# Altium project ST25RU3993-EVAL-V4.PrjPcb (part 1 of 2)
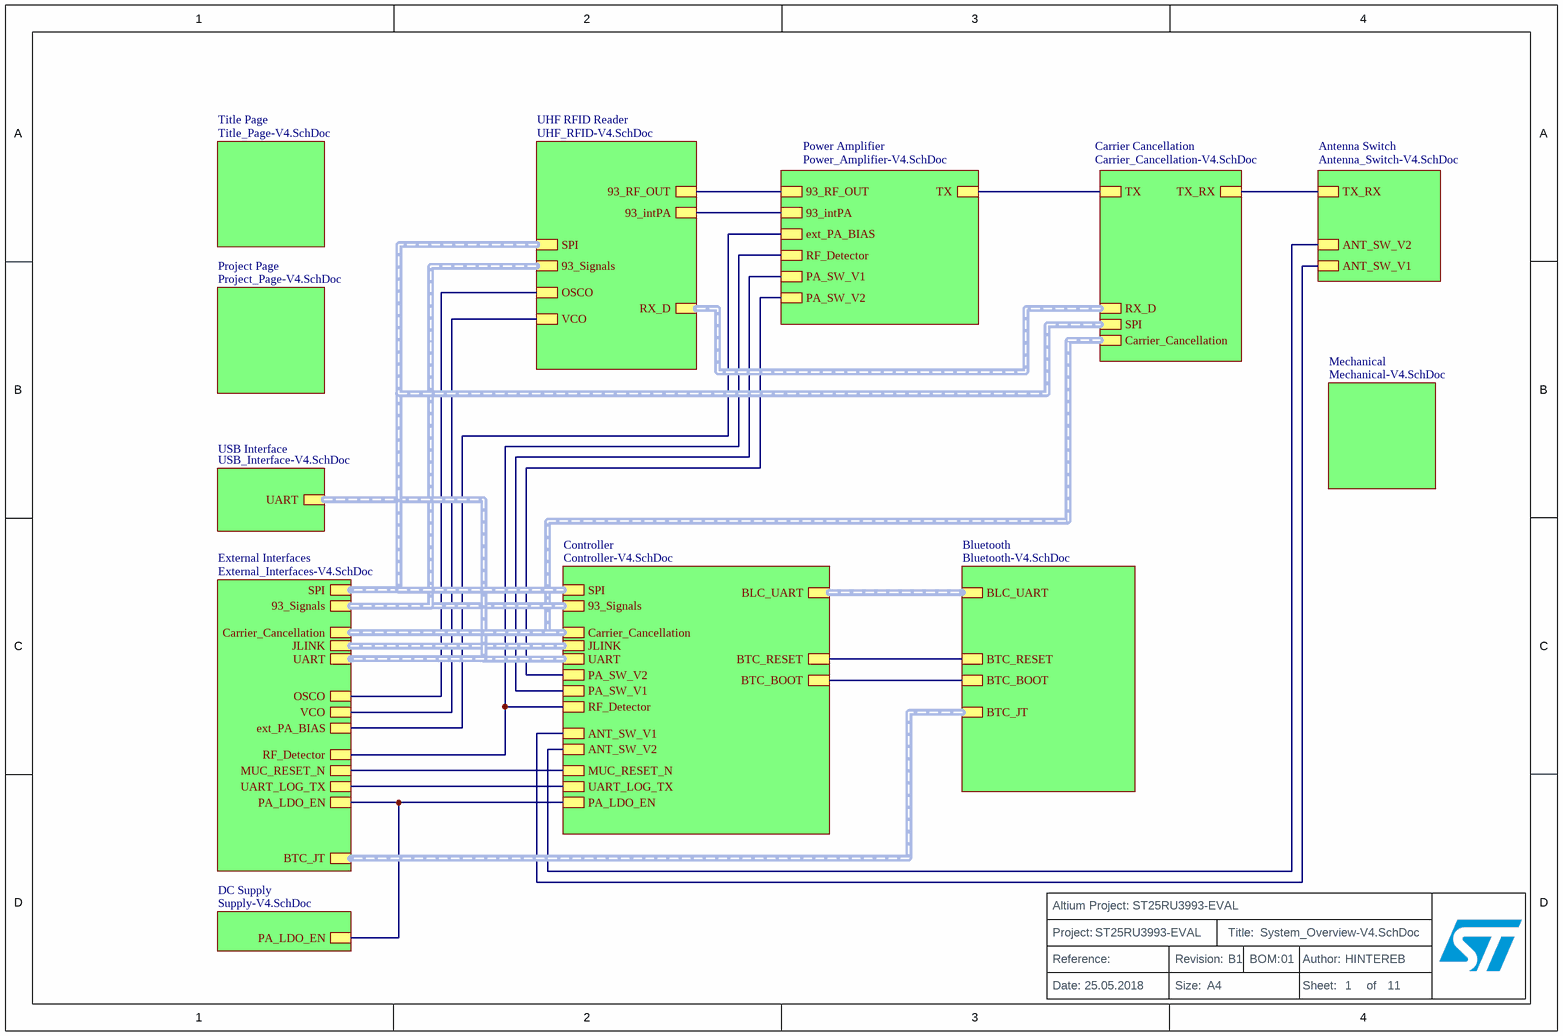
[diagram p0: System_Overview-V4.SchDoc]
ApplicationEngineer: HINTEREB; BoardCat: EVAL; BoardRef: None; BoardtypeVersion: B1; BOM Version: 01; ProjTitle: ST25RU3993-EVAL; ReleaseDate: 25.05.2018; SocProj: ST25RU3993-EVAL; SupportingApplicationEngineer: HOFERFLO; TotalNumberofSheets: 11; Variant: Standard; Version: B1
13 sheets, 327 parts. Net scope: hierarchical (ports join the sheet entries above them; power ports are global).
Board file: ST25RU3993-EVAL-V4.PcbDoc
Sheets:
  System_Overview-V4.SchDoc
    UHF RFID Reader = UHF_RFID-V4.SchDoc
    Power Amplifier = Power_Amplifier-V4.SchDoc
    Project Page = Project_Page-V4.SchDoc
    External Interfaces = External_Interfaces-V4.SchDoc
    Controller = Controller-V4.SchDoc
    Carrier Cancellation = Carrier_Cancellation-V4.SchDoc
    DC Supply = Supply-V4.SchDoc
    Title Page = Title_Page-V4.SchDoc
    USB Interface = USB_Interface-V4.SchDoc
    Bluetooth = Bluetooth-V4.SchDoc
    Mechanical = Mechanical-V4.SchDoc
    Antenna Switch = Antenna_Switch-V4.SchDoc

## Sheet System_Overview-V4.SchDoc
size A4; SheetNumber: 1; PageSetup: Record=PageOptions¦CenterHorizontal=True¦CenterVertical=True¦PrintScale=0.97¦XCorrection=1.00¦YCorrection=1.00¦PrintKind=0¦BorderSize=5000000¦LeftOffset=0¦BottomOffset=0¦Orientation=2¦PaperLength=1000¦PaperWidth=1000¦Scale=100¦PaperSource=7¦PrintQuality=-3¦MediaType=1¦DitherType=10¦PrintScaleMode=1¦PaperKind=A4¦PaperIndex=9

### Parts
TitleBlock7  Title_Block  (value not drawn)  (no BOM)

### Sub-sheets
Antenna Switch = Antenna_Switch-V4.SchDoc: ANT_SW_V2, TX_RX, ANT_SW_V1
Bluetooth = Bluetooth-V4.SchDoc: BLC_UART (harness Harness_UART_BT), BTC_JT, BTC_RESET, BTC_BOOT
Carrier Cancellation = Carrier_Cancellation-V4.SchDoc: TX, Carrier_Cancellation (harness Harness_CC), SPI (harness Harness_SPI), RX_D (harness Harness_RX_D), TX_RX
Controller = Controller-V4.SchDoc: SPI (harness Harness_SPI), UART (harness Harness_UART), 93_Signals (harness Harness_93), JLINK (harness Harness_JLINK), Carrier_Cancellation (harness Harness_CC), PA_LDO_EN, PA_SW_V2, MUC_RESET_N, UART_LOG_TX, BLC_UART (harness Harness_UART_BT), BTC_RESET, ANT_SW_V1, RF_Detector, PA_SW_V1, ANT_SW_V2, BTC_BOOT
DC Supply = Supply-V4.SchDoc: PA_LDO_EN
External Interfaces = External_Interfaces-V4.SchDoc: SPI (harness Harness_SPI), 93_Signals (harness Harness_93), Carrier_Cancellation (harness Harness_CC), JLINK (harness Harness_JLINK), PA_LDO_EN, MUC_RESET_N, UART_LOG_TX, BTC_JT (harness Harness_BTC_JT), OSCO, VCO, ext_PA_BIAS, RF_Detector, UART (harness Harness_UART)
Mechanical = Mechanical-V4.SchDoc: no entries
Power Amplifier = Power_Amplifier-V4.SchDoc: 93_RF_OUT, TX, PA_SW_V2, RF_Detector, 93_intPA, ext_PA_BIAS, PA_SW_V1
Project Page = Project_Page-V4.SchDoc: no entries
Title Page = Title_Page-V4.SchDoc: no entries
UHF RFID Reader = UHF_RFID-V4.SchDoc: 93_RF_OUT, SPI (harness Harness_SPI), 93_Signals (harness Harness_93), RX_D (harness Harness_RX_D), 93_intPA, OSCO, VCO
USB Interface = USB_Interface-V4.SchDoc: UART (harness Harness_UART)

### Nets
Detector: sheet Power Amplifier/RF_Detector, sheet External Interfaces/RF_Detector, sheet Controller/RF_Detector
EXT_PA_BIAS: sheet Power Amplifier/ext_PA_BIAS, sheet External Interfaces/ext_PA_BIAS
OSCO: sheet UHF RFID Reader/OSCO, sheet External Interfaces/OSCO
PA_LDO_EN: sheet External Interfaces/PA_LDO_EN, sheet Controller/PA_LDO_EN, sheet DC Supply/PA_LDO_EN
UART_LOG_TX: sheet External Interfaces/UART_LOG_TX, sheet Controller/UART_LOG_TX
VCO: sheet UHF RFID Reader/VCO, sheet External Interfaces/VCO
NetB1_1: sheet External Interfaces/MUC_RESET_N, sheet Controller/MUC_RESET_N
NetC107_1: sheet UHF RFID Reader/93_intPA, sheet Power Amplifier/93_intPA
NetC112_2: sheet Carrier Cancellation/TX_RX, sheet Antenna Switch/TX_RX
NetJ1_IN: sheet UHF RFID Reader/93_RF_OUT, sheet Power Amplifier/93_RF_OUT
NetJ19_1: sheet Controller/BTC_BOOT, sheet Bluetooth/BTC_BOOT
NetR74_1: sheet Controller/BTC_RESET, sheet Bluetooth/BTC_RESET
NetS1_1: sheet Power Amplifier/PA_SW_V1, sheet Controller/PA_SW_V1
NetS1_3: sheet Power Amplifier/PA_SW_V2, sheet Controller/PA_SW_V2
NetS2_1: sheet Controller/ANT_SW_V1, sheet Antenna Switch/ANT_SW_V1
NetS2_3: sheet Controller/ANT_SW_V2, sheet Antenna Switch/ANT_SW_V2
NetT2_1: sheet Power Amplifier/TX, sheet Carrier Cancellation/TX

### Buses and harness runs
harness sheet Bluetooth/BLC_UART = sheet Controller/BLC_UART
harness sheet Bluetooth/BTC_JT = sheet External Interfaces/BTC_JT
harness sheet Carrier Cancellation/Carrier_Cancellation = sheet Controller/Carrier_Cancellation = sheet External Interfaces/Carrier_Cancellation
harness sheet Carrier Cancellation/RX_D = sheet UHF RFID Reader/RX_D
harness sheet Carrier Cancellation/SPI = sheet Controller/SPI = sheet External Interfaces/SPI = sheet UHF RFID Reader/SPI
harness sheet Controller/93_Signals = sheet External Interfaces/93_Signals = sheet UHF RFID Reader/93_Signals
harness sheet Controller/JLINK = sheet External Interfaces/JLINK
harness sheet Controller/UART = sheet External Interfaces/UART = sheet USB Interface/UART

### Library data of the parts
TitleBlock7 = Title_Block: Exact Component Match: no

## Sheet UHF_RFID-V4.SchDoc
size A4; SheetNumber: 2; PageSetup: Record=PageOptions¦CenterHorizontal=True¦CenterVertical=True¦PrintScale=0.97¦XCorrection=1.00¦YCorrection=1.00¦PrintKind=0¦BorderSize=5000000¦LeftOffset=0¦BottomOffset=0¦Orientation=2¦PaperLength=1000¦PaperWidth=1000¦Scale=100¦PaperSource=7¦PrintQuality=-4¦MediaType=1¦DitherType=10¦PaperKind=A4¦PrintScaleMode=1
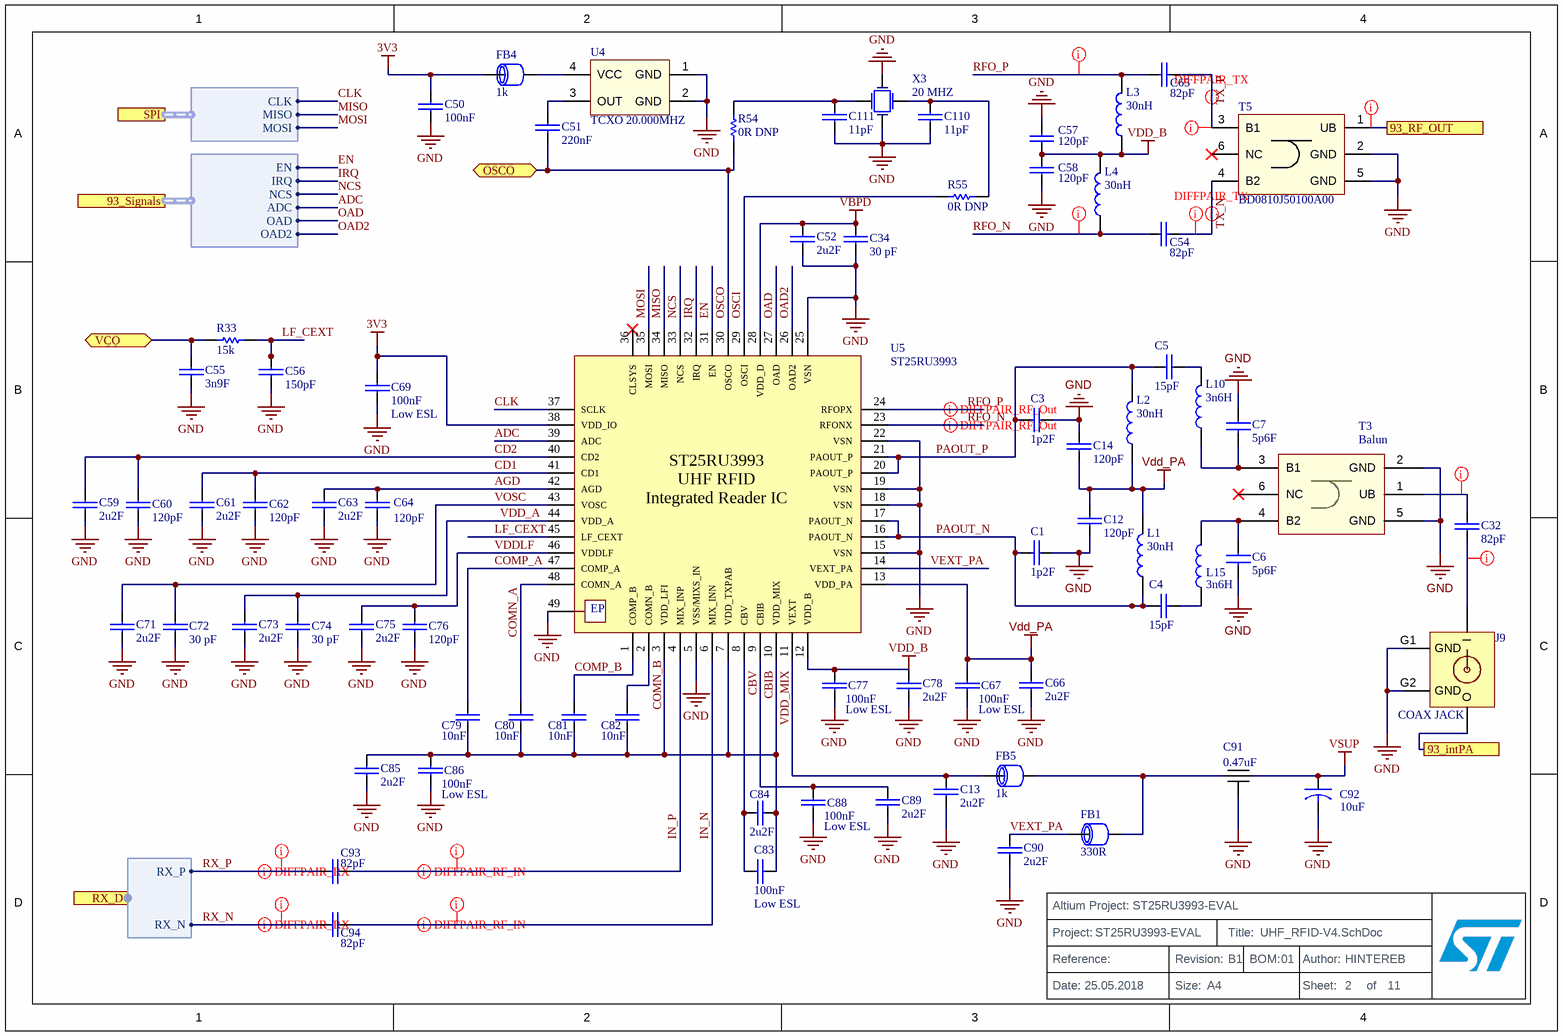
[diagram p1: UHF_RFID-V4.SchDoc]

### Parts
C1  1p2F  [C0402-RF]
C3  1p2F  [C0402-RF]
C4  15pF  [C0402-RF]
C5  15pF  [C0402-RF]
C6  5p6F  [C0402-RF]
C7  5p6F  [C0402-RF]
C12  120pF  [C0201-RF]
C13  2u2F  [C0201-RF]
C14  120pF  [C0201-RF]
C32  82pF  [C0402-RF]
C34  30 pF  [C0201-RF]
C50  100nF  [C0402-RF]
C51  220nF  [C0402-RF]
C52  2u2F  [C0201-RF]
C54  82pF  [C0402-RF]
C55  3n9F  [C0402-RF]
C56  150pF  [C0402-RF]
C57  120pF  [C0201-RF]
C58  120pF  [C0201-RF]
C59  2u2F  [C0201-RF]
C60  120pF  [C0201-RF]
C61  2u2F  [C0201-RF]
C62  120pF  [C0201-RF]
C63  2u2F  [C0201-RF]
C64  120pF  [C0201-RF]
C65  82pF  [C0402-RF]
C66  2u2F  [C0201-RF]
C67  100nF  Features: Low ESL  [C0402-LLL]
C69  100nF  Features: Low ESL  [C0402-LLL]
C71  2u2F  [C0201-RF]
C72  30 pF  [C0201-RF]
C73  2u2F  [C0201-RF]
C74  30 pF  [C0201-RF]
C75  2u2F  [C0201-RF]
C76  120pF  [C0201-RF]
C77  100nF  Features: Low ESL  [C0402-LLL]
C78  2u2F  [C0201-RF]
C79  10nF  [C0201-ss]
C80  10nF  [C0201-ss]
C81  10nF  [C0201-ss]
C82  10nF  [C0201-ss]
C83  100nF  Features: Low ESL  [C0402-LLL]
C84  2u2F  [C0201-RF]
C85  2u2F  [C0201-RF]
C86  100nF  Features: Low ESL  [C0402-LLL]
C88  100nF  Features: Low ESL  [C0402-LLL]
C89  2u2F  [C0201-RF]
C90  2u2F  [C0201-RF]
C91  0.47uF  [NFM18PS]
C92  10uF  [2917(7343)]
C93  82pF  [C0402-RF]
C94  82pF  [C0402-RF]
C110  11pF  [C0402-RF]
C111  11pF  [C0402-RF]
FB1  330R  [FB0402-RF]
FB4  1k  [L0402-RF]
FB5  1k  [L0402-RF]
J9  COAX JACK  [MS-156HF]
L1  30nH  [L0402-RF]
L2  30nH  [L0402-RF]
L3  30nH  [L0402-RF]
L4  30nH  [L0402-RF]
L10  3n6H  [L0402-RF]
L15  3n6H  [L0402-RF]
R33  15k  [R0402-RF]
R54  0R DNP  [R0402-RF]
R55  0R DNP  [R0402-RF]
T3  Balun  [JTI-0900BL15C050]
T5  BD0810J50100A00  [BD0810J50100AHF]
TitleBlock5  Title_Block  (value not drawn)  (no BOM)
U4  TCXO 20.000MHZ  [3.2 x 2.5 mm SMD]
U5  ST25RU3993  [ST25RU3993_QFN48_0.5mm_pitch]
X3  20 MHZ  [NX3225SA]

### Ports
93_intPA, 93_RF_OUT, 93_Signals (harness Harness_93), OSCO (bidir), RX_D (harness Harness_RX_D), SPI (harness Harness_SPI), VCO (bidir)

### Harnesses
Harness_SPI: MISO, MOSI, CLK
Harness_93: IRQ, EN, NCS, ADC, OAD, OAD2
Harness_RX_D: RX_P, RX_N

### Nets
3V3: C50.1 C69.1 FB4.1 U5.38(VDD_IO)
GND: C1.2 C3.2 C6.2 C7.1 C12.2 C13.2 C14.1 C34.2 C50.2 C52.1 C55.2 C56.2 C57.1 C58.2 C59.2 C60.2 C61.2 C62.2 C63.2 C64.2 C66.2 C67.2 C69.2 C71.2 C72.2 C73.2 C74.2 C75.2 C76.2 C77.2 C78.2 C85.2 C86.2 C88.2 C89.2 C90.2 C91.2 C92.2 C110.2 C111.2 J9.G1(GND) J9.G2(GND) T3.2(GND) T3.5(GND) T5.2(GND) T5.5(GND) U4.1(GND) U4.2(GND) U5.5(VSS/MIXS_IN) U5.15(VSN) U5.18(VSN) U5.19(VSN) U5.22(VSN) U5.25(VSN) U5.49(EP) X3.2(GND) X3.4(GND)
VBPD: C34.1 C52.2 U5.28(VDD_D)
VDD_B: C57.2 C58.1 C77.1 C78.1 L3.1 L4.2 U5.12(VDD_B)
Vdd_PA: C12.1 C14.2 C66.1 C67.1 L1.2 L2.1 U5.13(VDD_PA)
VSUP: C91.3 C92.1
ADC: U5.39(ADC) ; port 93_Signals.ADC
AGD: C63.1 C64.1 U5.42(AGD)
CBIB: C88.1 C89.1 U5.9(CBIB)
CBV: C83.1 C84.1 U5.8(CBV)
CD1: C61.1 C62.1 U5.41(CD1)
CD2: C59.1 C60.1 U5.40(CD2)
CLK: U5.37(SCLK) ; port SPI.CLK
COMN_A: C80.1 U5.48(COMN_A)
COMN_B: C82.1 U5.2(COMN_B)
COMP_A: C79.1 U5.47(COMP_A)
COMP_B: C81.1 U5.1(COMP_B)
EN: U5.31(EN) ; port 93_Signals.EN
IN_N: C94.2 U5.6(MIX_INN)
IN_P: C93.2 U5.4(MIX_INP)
IRQ: U5.32(IRQ) ; port 93_Signals.IRQ
LF_CEXT: C56.1 R33.2 U5.45(LF_CEXT)
MISO: U5.34(MISO) ; port SPI.MISO
MOSI: U5.35(MOSI) ; port SPI.MOSI
NCS: U5.33(NCS) ; port 93_Signals.NCS
OAD: U5.27(OAD) ; port 93_Signals.OAD
OAD2: U5.26(OAD2) ; port 93_Signals.OAD2
OSCI: R55.2 U5.29(OSCI)
OSCO: C51.2 R54.1 U5.30(OSCO) ; port OSCO
PAOUT_N: C1.1 C4.1 L1.1 U5.16(PAOUT_N) U5.17(PAOUT_N)
PAOUT_P: C3.1 C5.1 L2.2 U5.20(PAOUT_P) U5.21(PAOUT_P)
RFO_N: C54.1 L4.1 U5.23(RFONX)
RFO_P: C65.1 L3.2 U5.24(RFOPX)
RX_N: C94.1 ; port RX_D.RX_N
RX_P: C93.1 ; port RX_D.RX_P
TX_N: C54.2 T5.4(B2)
TX_P: C65.2 T5.3(B1)
VCO: C55.1 R33.1 ; port VCO
VDD_A: C73.1 C74.1 U5.44(VDD_A)
VDD_MIX: C79.2 C80.2 C81.2 C82.2 C83.2 C84.2 C85.1 C86.1 U5.3(VDD_LFI) U5.7(VDD_TXPAB) U5.10(VDD_MIX)
VDDLF: C75.1 C76.1 U5.46(VDDLF)
VEXT_PA: C90.1 FB1.1 U5.14(VEXT_PA)
VOSC: C71.1 C72.1 U5.43(VOSC)
NetC4_2: C4.2 L15.1
NetC5_2: C5.2 L10.2
NetC6_1: C6.1 L15.2 T3.4(B2)
NetC7_2: C7.2 L10.1 T3.3(B1)
NetC13_1: C13.1 FB5.1 U5.11(VEXT)
NetC32_1: C32.1 J9.IN(I)
NetC32_2: C32.2 T3.1(UB)
NetC51_1: C51.1 U4.3(OUT)
NetC91_1: C91.1 FB1.2 FB5.2
NetC107_1: J9.OUT(O) ; port 93_intPA
NetC110_1: C110.1 R55.1 X3.3
NetC111_1: C111.1 R54.2 X3.1
NetFB4_2: FB4.2 U4.4(VCC)
NetJ1_IN: T5.1(UB) ; port 93_RF_OUT

Not connected (* = marked no-connect by the designer): T3 6(NC)*; T5 6(NC)*; U5 36(CLSYS)*

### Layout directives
net class SE_CPWG: NetC32_1, NetC32_2, NetJ1_IN
differential pair: IN_N, IN_P, RFO_N, RFO_P, RX_N, RX_P, TX_N, TX_P
net class Differential_RF: IN_N, IN_P, RFO_N, RFO_P, RX_N, RX_P, TX_N, TX_P

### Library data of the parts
C1 C3 = GRM1555C1H1R2WA01D: CAP CER 1.2PF 50V NP0 0402; Manufacturer: Murata Electronics North America; Tolerance: ±0.05pF; Temperature Coefficient: C0G, NP0; Exact Component Match: yes
C4 C5 = GRM1555C1H150GA01D: CAP CER 15PF 50V NP0 0402; Manufacturer: Murata Electronics North America; Tolerance: ±2%; Temperature Coefficient: C0G, NP0; Exact Component Match: yes
C6 C7 = GJM1555C1H5R6CB01D: CAP CER 5.6PF 50V NP0 0402; Manufacturer 1: Murata Electronics North America; Tolerance: ±0.25pF; Temperature Coefficient: C0G, NP0; Frequency Min: 380; Frequency Max: 960; Gain: 32; RF IC Case Style: QFN; No. of Pins: 16; Supply Voltage Min: 3; Supply Voltage Max: 5; Frequency Range: 380MHz to 960; RF Type: General Purpose; Supply Current: 320; Supply Voltage Range: 3V to 5V<!--FANDB--><div class="features-and-benefits-container"><div class="features-and-benefits-description"><span class="features-benefits-value">The RFPA0133 is a 3 to 5V high efficiency programmable gain Power Amplifier designed to offer saturated efficiency greater than 60% over a range of frequencies from 380 to 960MHz. The device is manufactured on an advanced Gallium Arsenide Heterojunction Bipolar Transistor (HBT) process.</span></div><div class="features-and-benefits-list"><ul class="features-and-benefits-list-list"><li class="features-and-benefits-list-item">0.5W CW Output power at 3.6V</li><li class="features-and-benefits-list-item">1W CW Output power at 5V</li><li class="features-and-benefits-list-item">32dB Small signal gain at 900; Exact Component Match: yes
C12 C14 C57 C58 C60 C62 C64 C76 = GRM0335C1H121JA01D: CAP CER 120PF 50V C0G/NP0 0201; Manufacturer: Murata Electronics North America; Tolerance: ±5%; Temperature Coefficient: C0G, NP0; Exact Component Match: no
C13 C52 C59 C61 C63 C66 C71 C73 C75 C78 C84 C85 C89 C90 = GRM033R60J225ME15D: CAP CER 2.2UF 6.3V X5R 0201; Manufacturer 1: Murata Electronics North America; Capacitance: 2.2µF; Tolerance: ±20%; Exact Component Match: no
C32 C54 C65 C93 C94 = GRM1555C1H820GA01J: CAP CER 82PF 50V C0G/NP0 0402; Manufacturer: Murata Electronics North America; Tolerance: ±2%; Temperature Coefficient: C0G, NP0; Filter Type: Signal Line; Number of Lines: 1; Impedance @ Frequency: 1 kOhm @ 100MHz; Current Rating (Max): 250mA; DC Resistance (DCR) (Max): 1.1 Ohm; Type: Zener; Voltage - Reverse Standoff (Typ): 3V; Voltage - Breakdown (Min): 6V; Voltage - Clamping (Max) @ Ipp: 17V; Current - Peak Pulse (10/1000µs): 1A (8/20µs); Power - Peak Pulse: 40W; Power Line Protection: No; Capacitance @ Frequency: 0.4pF @ 200MHz ~ 3GHz
C34 C72 C74 = GRM0335C1H300GA01D: CAP CER 30PF 50V C0G/NP0 0201; Manufacturer: Murata Electronics North America; Tolerance: ±2%; Temperature Coefficient: C0G, NP0; Exact Component Match: no
C50 = GRM155R71C104KA88D: CAP CER 0.1UF 16V X7R 0402; Manufacturer: Murata Electronics North America; Capacitance: 0.10µF; Tolerance: ±10%; Exact Component Match: no
C51 = GRM155R6YA224KE01D: CAP CER 0.22UF 35V X5R 0402; Manufacturer: Murata Electronics North America; Tolerance: ±10%; Exact Component Match: no
C55 = GRM1557U1A392JA01D: CAP CER 3900PF 10V U2J 0402; Manufacturer: Murata Electronics North America; Tolerance: ±5%; Exact Component Match: no
C56 = GRM1555C1H151FA01D: CAP CER 150PF 50V NP0 0402; Manufacturer: Murata Electronics North America; Tolerance: ±1%; Temperature Coefficient: C0G, NP0; Notification: Current market demand for these product types have resulted in fluctuating and extending lead times. Lead times may differ.; Exact Component Match: no
C67 C69 C77 C83 C86 C88 = LLL153C80J104ME01E: CAP CER 0.1UF 6.3V X6S 0204; Manufacturer: Murata Electronics North America; Tolerance: ±20%; Type: Steering (Rail to Rail); Voltage - Reverse Standoff (Typ): 5.25V; Voltage - Breakdown (Min): 6V; Power - Peak Pulse: 500W; Power Line Protection: Yes; Exact Component Match: no
C79-C82 = GRM033R61E103KA12D: CAP CER 10000PF 10V X7R 0201; Manufacturer 1: Murata Electronics North America; Manufacturer Part Number 1: GRM033R71A103KA01D; Tolerance: ±10%; Exact Component Match: no
C91 = NFM18PS474R0J3D: CAP FEEDTHRU 0.47UF 6.3V 0603; Manufacturer: Murata Electronics North America; Capacitance: 0.47µF; Tolerance: ±20%; Current: 2A; DC Resistance (DCR) (Max): 30 mOhm; Type: Polymer; ESR (Equivalent Series Resistance): 70 mOhm; Lifetime @ Temp.: 1000 Hrs @ 105°C; Ripple Current - High Frequency: 1A @ 100kHz; Surface Mount Land Size: 0.287" L x 0.169" W (7.30mm x 4.30mm); Exact Component Match: no
C92 = ECASD41C106M060K00: CAP POLYMER 10UF 20% 16V SMD; Manufacturer: Murata; Product Training Modules: Polymer Aluminum Electrolytic Capacitors Using Murata's Polymer Aluminum Capacitors to Replace Tantalum; Catalog Drawings: ECAS Series End_D4 ECAS Series Side; Featured Product: ECAS Series Polymer Aluminum Electrolytic Capacitors; EDA / CAD Models: Download from Accelerated Designs; Capacitance: 10µF; ESR (Equivalent Series Resistance): 60 mOhm @ 100kHz; Lifetime @ Temp.: 1000 Hrs @ 105°C; Polarization: Polar; Ripple Current: 1A; Surface Mount Land Size: 0.287" L x 0.169" W (7.30mm x 4.30mm); Online Catalog: ECAS Series; Other Names: 490-5482-2
C110 C111 = GJM1555C1H110GB01D (2): CAP CER 11PF 50V C0G/NP0 0402; Manufacturer: Murata Electronics North America; Tolerance: ±2%; Temperature Coefficient: C0G, NP0; Exact Component Match: no
FB1 = BLM15PX331SN1D: FERRITE BEAD 330 OHM 0402 1LN; Manufacturer: Murata Electronics North America; Filter Type: Power Line; Current Rating (Max): 1.2A; DC Resistance (DCR) (Max): 150 mOhm; Exact Component Match: no
FB4 FB5 = BLM15HG102SN1D: FERRITE BEAD 1 KOHM 0402 1LN; Manufacturer: Murata Electronics North America; Filter Type: Signal Line; Number of Lines: 1; Impedance @ Frequency: 1 kOhm @ 100MHz; Current Rating (Max): 250mA; DC Resistance (DCR) (Max): 1.1 Ohm; Exact Component Match: no
J9 = MS-156HF: CONN COAX JACK STR 50 OHM SMD; Manufacturer 1: Hirose Electric Co Ltd; Manufacturer Part Number 1: MS-156HF(01); Connector Style: Coaxial Switch - 4mm Plug Dia; Connector Type: Receptacle, Female Socket; Contact Termination: Solder; Impedance: 50 Ohm; Frequency - Max: 6GHz; Body Material: Phosphor Bronze; Body Finish: Gold; Center Contact Material: Beryllium Copper; Dielectric Material: Polyamide (PA), Nylon 6T; Coupler Type: Standard; Frequency: 700MHz ~ 1GHz; Coupling Factor: 10.9dB; Insertion Loss: 0.21dB; Power - Max: 2W; Return Loss: 17.5dB; Exact Component Match: no
L1 L2 = LQW15AN30NG00D: FIXED IND 30NH 270MA 580 MOHM; Manufacturer: Murata Electronics North America; Type: Wirewound; Material - Core: Non-Magnetic; Tolerance: ±2%; Shielding: Unshielded; DC Resistance (DCR): 580 mOhm Max; Q @ Freq: 25 @ 250MHz; Frequency - Self Resonant: 3.3GHz; Frequency - Test: 100MHz; Exact Component Match: yes
L3 L4 = LQW15AN30NG00D: FIXED IND 30NH 270MA 580 MOHM; Manufacturer: Murata Electronics North America; Type: Wirewound; Material - Core: Non-Magnetic; Tolerance: ±2%; Shielding: Unshielded; DC Resistance (DCR): 580 mOhm Max; Q @ Freq: 25 @ 250MHz; Frequency - Self Resonant: 3.3GHz; Frequency - Test: 100MHz; Exact Component Match: no
L10 L15 = LQW15AN3N6C10D: FIXED IND 3.6NH 900MA 40 MOHM; Manufacturer: Murata Electronics North America; Type: Wirewound; Material - Core: Non-Magnetic; Tolerance: ±0.2nH; Shielding: Unshielded; DC Resistance (DCR): 40 mOhm Max; Q @ Freq: 30 @ 250MHz; Frequency - Self Resonant: 9.5GHz; Frequency - Test: 100MHz; Exact Component Match: yes
R33 = ERJ-2GEJ153X: RES SMD 15K OHM 5% 1/10W 0402; Manufacturer: Panasonic Electronic Components; Power (Watts): 0.1W, 1/10W; Temperature Coefficient: ±200ppm/°C; Exact Component Match: no
R54 R55 = RC0402JR-070RL: RES SMD 0.0OHM JUMPER 1/16W 0402; Manufacturer: Yageo; Resistance (Ohms): 0.0; Power (Watts): 0.063W, 1/16W; Exact Component Match: no
T3 = 1:1 BALUN 900MHZ - 0900BL15C050: 1:1 BALUN- 900MHZ 50/50 Ohm; Manufacturer: Johanson Technology Inc; Manufacturer Part Number: 0900BL15C050E; Component_Description: BALUN GSM/DCS/PCS/CDMA 900MHZ; Frequency Range: 800 ~ 1000MHz; Phase Difference: 180° ±10; Insertion Loss (Max): 1.2dB; Return Loss (Min): 9.5dB; Exact Component Match: no
T5 = BD0810J50100AHF: XFRMR BALUN RF 800-1000MHZ 0805; Manufacturer: Anaren; Frequency Range: 800MHz ~ 1GHz; Impedance - Unbalanced/Balanced: 50 / 100 Ohm; Phase Difference: 1°; Insertion Loss (Max): 0.95dB; Return Loss (Min): 13dB; Exact Component Match: no
TitleBlock5 = Title_Block: Exact Component Match: no
U4 = TXETDCSANF-20.000000: OSC TCXO 20.0000MHZ CLP SW SMD; Manufacturer: Taitien; Output: Clipped Sine Wave; Voltage - Supply: 2.8 V ~ 3.3 V; Frequency Stability: ±2.5ppm; Current - Supply (Max): 2mA
U5 = ST25RU3993: UHF EPC CLASS1 GEN2 READER; Manufacturer: ST Microelectronics; Manufacturer Part Number: ST25RU3993-BQFT; Frequency: 860MHz ~ 960MHz; Standards: EPC, ISO 18000-6; Voltage - Supply: 2.7 V ~ 3.6 V; Exact Component Match: yes
X3 = NX3225SA-20.000000MHZ-B2: CRYSTAL 20.0000MHZ 7.2PF SMD; Manufacturer: NDK; Frequency: 20MHz; Frequency Stability: ±15ppm; Frequency Tolerance: ±10ppm; ESR (Equivalent Series Resistance): 80 Ohm; Operating Mode: Fundamental; Exact Component Match: no

## Sheet Power_Amplifier-V4.SchDoc
size A4; SheetNumber: 3; PageSetup: Record=PageOptions¦CenterHorizontal=True¦CenterVertical=True¦PrintScale=0.97¦XCorrection=1.00¦YCorrection=1.00¦PrintKind=0¦BorderSize=5000000¦LeftOffset=0¦BottomOffset=0¦Orientation=2¦PaperLength=1000¦PaperWidth=1000¦Scale=100¦PaperSource=7¦PrintQuality=-4¦MediaType=1¦DitherType=10¦PaperKind=A4¦PrintScaleMode=1
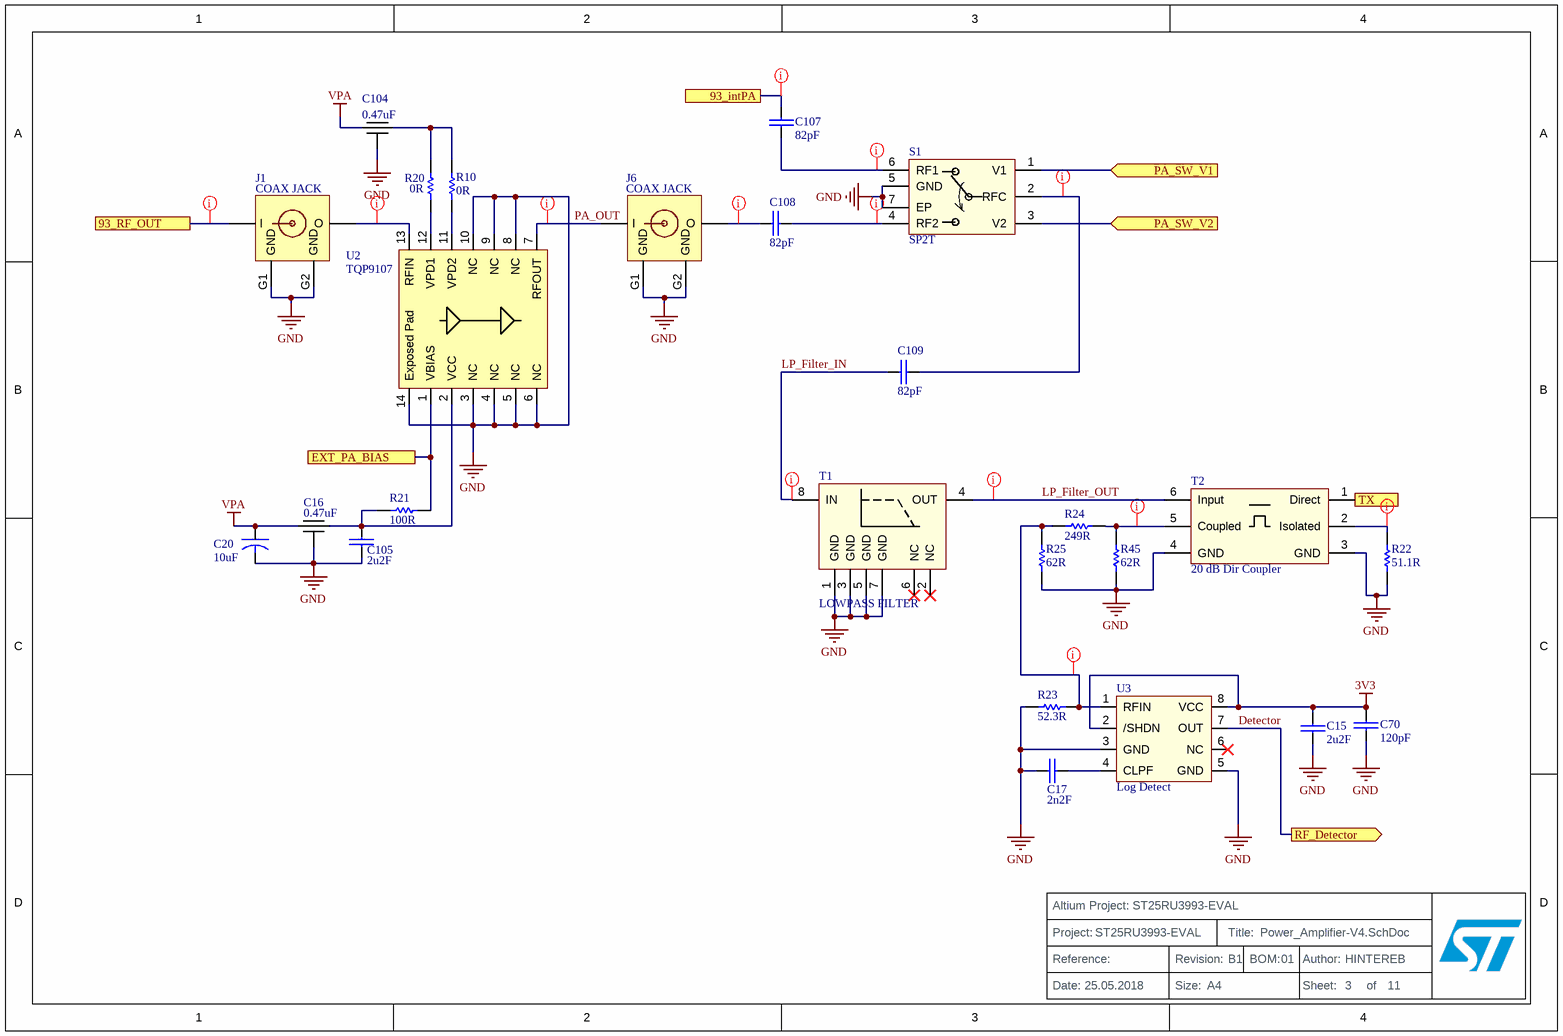
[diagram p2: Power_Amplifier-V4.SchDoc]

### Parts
C15  2u2F  [C0201-RF]
C16  0.47uF  [NFM18PS]
C17  2n2F  [C0402-RF]
C20  10uF  [2917(7343)]
C70  120pF  [C0201-RF]
C104  0.47uF  [NFM18PS]
C105  2u2F  [C0201-RF]
C107  82pF  [C0402-RF]
C108  82pF  [C0402-RF]
C109  82pF  [C0402-RF]
J1  COAX JACK  [MS-156HF_SAW]
J6  COAX JACK  [MS-156HF]
R10  0R  [R0402-RF]
R20  0R  [R0402-RF]
R21  100R  [R0402-RF]
R22  51.1R  [R0402-RF]
R23  52.3R  [R0402-RF]
R24  249R  [R0402-RF]
R25  62R  [R0402-RF]
R45  62R  [R0402-RF]
S1  SP2T  [SKY13431-374LF]
T1  LOWPASS FILTER  [JTI-0900LP15B0063]
T2  20 dB Dir Coupler  [DC0710J5010AHF]
TitleBlock3  Title_Block  (value not drawn)  (no BOM)
U2  TQP9107  [TQP9107]
U3  Log Detect  [MAX4003]

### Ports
93_intPA, 93_RF_OUT, EXT_PA_BIAS, PA_SW_V1 (in), PA_SW_V2 (in), RF_Detector (out), TX (out)

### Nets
3V3: C15.1 C70.1 U3.2(/SHDN) U3.8(VCC)
GND: C15.2 C16.2 C17.1 C20.2 C70.2 C104.2 C105.2 J1.G1(GND) J1.G2(GND) J6.G1(GND) J6.G2(GND) R22.1 R23.1 R25.1 R45.1 S1.5(GND) S1.7(EP) T1.1(GND) T1.3(GND) T1.5(GND) T1.7(GND) T2.3(GND) T2.4(GND) U2.3(NC) U2.4(NC) U2.5(NC) U2.6(NC) U2.8(NC) U2.9(NC) U2.10(NC) U2.14(Exposed_Pad) U3.3(GND) U3.5(GND)
VPA: C16.3 C20.1 C104.1
Detector: U3.7(OUT) ; port RF_Detector
EXT_PA_BIAS: R21.2 U2.1(VBIAS) ; port EXT_PA_BIAS
LP_Filter_IN: C109.2 T1.8(IN)
LP_Filter_OUT: T1.4(OUT) T2.6(Input)
PA_OUT: J6.IN(I) U2.7(RFOUT)
NetC16_1: C16.1 C105.1 R21.1 U2.2(VCC)
NetC17_2: C17.2 U3.4(CLPF)
NetC104_3: C104.3 R10.2 R20.2
NetC107_1: C107.1 ; port 93_intPA
NetC107_2: C107.2 S1.6(RF1)
NetC108_1: C108.1 S1.4(RF2)
NetC108_2: C108.2 J6.OUT(O)
NetC109_1: C109.1 S1.2(RFC)
NetJ1_IN: J1.IN(I) ; port 93_RF_OUT
NetJ1_OUT: J1.OUT(O) U2.13(RFIN)
NetR10_1: R10.1 U2.11(VPD2)
NetR20_1: R20.1 U2.12(VPD1)
NetR22_2: R22.2 T2.2(Isolated)
NetR23_2: R23.2 R24.1 R25.2 U3.1(RFIN)
NetR24_2: R24.2 R45.2 T2.5(Coupled)
NetS1_1: S1.1(V1) ; port PA_SW_V1
NetS1_3: S1.3(V2) ; port PA_SW_V2
NetT2_1: T2.1(Direct) ; port TX

Not connected (* = marked no-connect by the designer): T1 2(NC)* 6(NC)*; U3 6(NC)*

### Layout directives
net class SE_CPWG: LP_Filter_IN, LP_Filter_OUT, NetC107_1, NetC107_2, NetC108_1, NetC108_2, NetC109_1, NetJ1_IN, NetJ1_OUT, NetR22_2, NetR23_2, NetR24_2, PA_OUT

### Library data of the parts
C15 C105 = GRM033R60J225ME15D: as C13 on sheet UHF_RFID-V4
C16 C104 = NFM18PS474R0J3D: as C91 on sheet UHF_RFID-V4
C17 = GRM155R71H222KA01D (2): CAP CER 2.2NF 50V X7R 0402; Manufacturer: Murata Electronics North America; Tolerance: ±10%; Notification: Current market demand for these product types have resulted in fluctuating and extending lead times. Lead times may differ.; Exact Component Match: no
C20 = ECASD41C106M060K00: as C92 on sheet UHF_RFID-V4
C70 = GRM0335C1H121JA01D: as C12 on sheet UHF_RFID-V4
C107-C109 = GRM1555C1H820GA01J: as C32 on sheet UHF_RFID-V4
J1 = MS-156HF_SAW: CONN COAX JACK STR 50 OHM SMD; Manufacturer 1: Hirose Electric Co Ltd; Manufacturer Part Number 1: MS-156HF(01); Connector Style: Coaxial Switch - 4mm Plug Dia; Connector Type: Receptacle, Female Socket; Contact Termination: Solder; Impedance: 50 Ohm; Frequency - Max: 6GHz; Body Material: Phosphor Bronze; Body Finish: Gold; Center Contact Material: Beryllium Copper; Dielectric Material: Polyamide (PA), Nylon 6T; Coupler Type: Standard; Frequency: 700MHz ~ 1GHz; Coupling Factor: 10.9dB; Insertion Loss: 0.21dB; Power - Max: 2W; Return Loss: 17.5dB; Exact Component Match: no; Capacitance: 2.2µF; Tolerance: ±20%; Voltage - Rated: 10V; Current: 4A; DC Resistance (DCR) (Max): 10 mOhm; Material - Core: Air; Shielding: Unshielded; DC Resistance (DCR): 1.25 Ohm Max
J6 = MS-156HF: as J9 on sheet UHF_RFID-V4
R10 R20 = RC0402JR-070RL: as R54 on sheet UHF_RFID-V4
R21 = RC0402FR-07100RL: RES SMD 100 OHM 1% 1/16W 0402; Manufacturer: Yageo; Resistance (Ohms): 100; Power (Watts): 0.063W, 1/16W; Temperature Coefficient: ±100ppm/°C; Exact Component Match: no
R22 = RC0402FR-0751R1L: RES SMD 51.1 OHM 1% 1/16W 0402; Manufacturer: Yageo; Power (Watts): 0.063W, 1/16W; Temperature Coefficient: ±100ppm/°C; Exact Component Match: no
R23 = ERJ2RKF52R3X: RES SMD 52R3 1% 0.1W 0402; Manufacturer: Panasonic Electronic Components; Manufacturer Part Number: ERJ-2RKF52R3X; Power (Watts): 0.1W, 1/10W; Temperature Coefficient: ±100ppm/°C; Exact Component Match: no
R24 = RC0402FR-07249RL: RES SMD 249 OHM 1% 1/16W 0402; Manufacturer: Yageo; Power (Watts): 0.063W, 1/16W; Temperature Coefficient: ±100ppm/°C; Exact Component Match: no
R25 R45 = RC0402FR-0762RL: RES SMD 62 OHM 1% 1/16W 0402; Manufacturer: Yageo; Power (Watts): 0.063W, 1/16W; Temperature Coefficient: ±100ppm/°C; Exact Component Match: no
S1 = SKY13431-374LF: IC SWITCH SP2T; Manufacturer: Skyworks Solutions Inc.; Frequency - Lower: 500MHz; Isolation @ Frequency: 20dB @ 5.8GHz (typ); Insertion Loss @ Frequency: 0.8dB @ 5.8GHz; IIP3: 57dBm (typ); Circuit: SPDT; P1dB: 36dBm; Impedance: 50 Ohm; Voltage - Supply: 2.5 V ~ 5 V; RF Type: WiMax, WLAN; Exact Component Match: no
T1 = 0900LP15B0063: FILTER LOWPASS 863-960MHZ; Manufacturer: Johanson Technology Inc.; Manufacturer Part Number: 0900LP15B0063E; Exact Component Match: no
T2 = DC1722J5020AHF: COUPLER 20DB 1700-2200MHZ 0805; Manufacturer: Anaren; Coupler Type: Standard; Frequency: 1.7GHz ~ 2.2GHz; Coupling Factor: 19.9dB; Insertion Loss: 0.17dB; Power - Max: 2W; Return Loss: 22.5dB; Exact Component Match: no
TitleBlock3 = Title_Block: Exact Component Match: no
U2 = TQP9107: 699 – 960 MHz 2-stage Power Amplifier; Manufacturer: Qorvo
U3 = MAX4003EUA+T: IC LOG AMP RF DETECT 45DB 8-MSOP; Manufacturer: Maxim Integrated; Frequency: 100MHz ~ 2.5GHz; RF Type: Cellular, TDMA, CDMA, GPRS, GSM; Input Range: -45dBm ~ 0dBm; Voltage - Supply: 2.7 V ~ 5 V; Exact Component Match: no

## Sheet Project_Page-V4.SchDoc
size A4
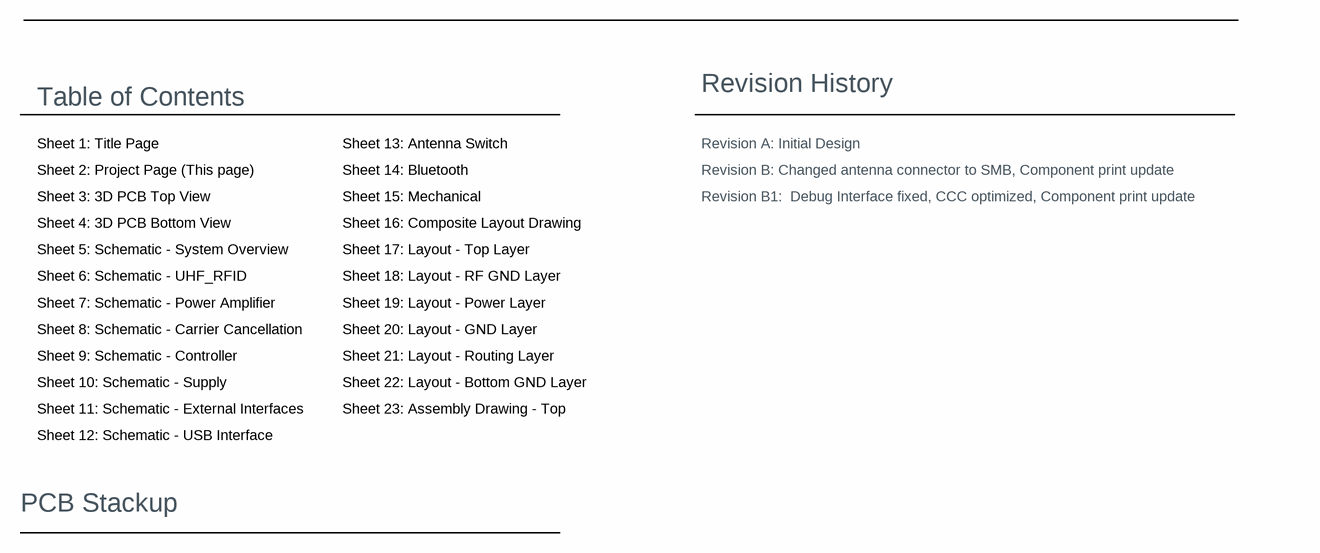
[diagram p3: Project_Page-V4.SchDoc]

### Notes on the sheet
- Table of Contents
- Sheet 1: Title Page
- Sheet 13: Antenna Switch
- Revision History
- Revision A: Initial Design
- Sheet 2: Project Page (This page)
- Sheet 3: 3D PCB Top View
- Sheet 15: Mechanical
- Sheet 14: Bluetooth
- Revision B: Changed antenna connector to SMB, Component print update
- Revision B1:  Debug Interface fixed, CCC optimized, Component print update
- Sheet 5: Schematic - System Overview
- Sheet 6: Schematic - UHF_RFID
- Sheet 4: 3D PCB Bottom View
- Sheet 17: Layout - Top Layer
- Sheet 18: Layout - RF GND Layer
- Sheet 16: Composite Layout Drawing
- Sheet 7: Schematic - Power Amplifier
- Sheet 8: Schematic - Carrier Cancellation
- Sheet 19: Layout - Power Layer
- Sheet 20: Layout - GND Layer
- Sheet 10: Schematic - Supply
- Sheet 11: Schematic - External Interfaces
- Sheet 9: Schematic - Controller
- Sheet 23: Assembly Drawing - Top
- Sheet 21: Layout - Routing Layer
- Sheet 22: Layout - Bottom GND Layer
- Sheet 12: Schematic - USB Interface
- PCB Stackup

## Sheet External_Interfaces-V4.SchDoc
size A4; SheetNumber: 7; PageSetup: Record=PageOptions¦CenterHorizontal=True¦CenterVertical=True¦PrintScale=0.97¦XCorrection=1.00¦YCorrection=1.00¦PrintKind=0¦BorderSize=5000000¦LeftOffset=0¦BottomOffset=0¦Orientation=2¦PaperLength=1000¦PaperWidth=1000¦Scale=100¦PaperSource=7¦PrintQuality=-4¦MediaType=1¦DitherType=10¦PaperKind=A4¦PrintScaleMode=1
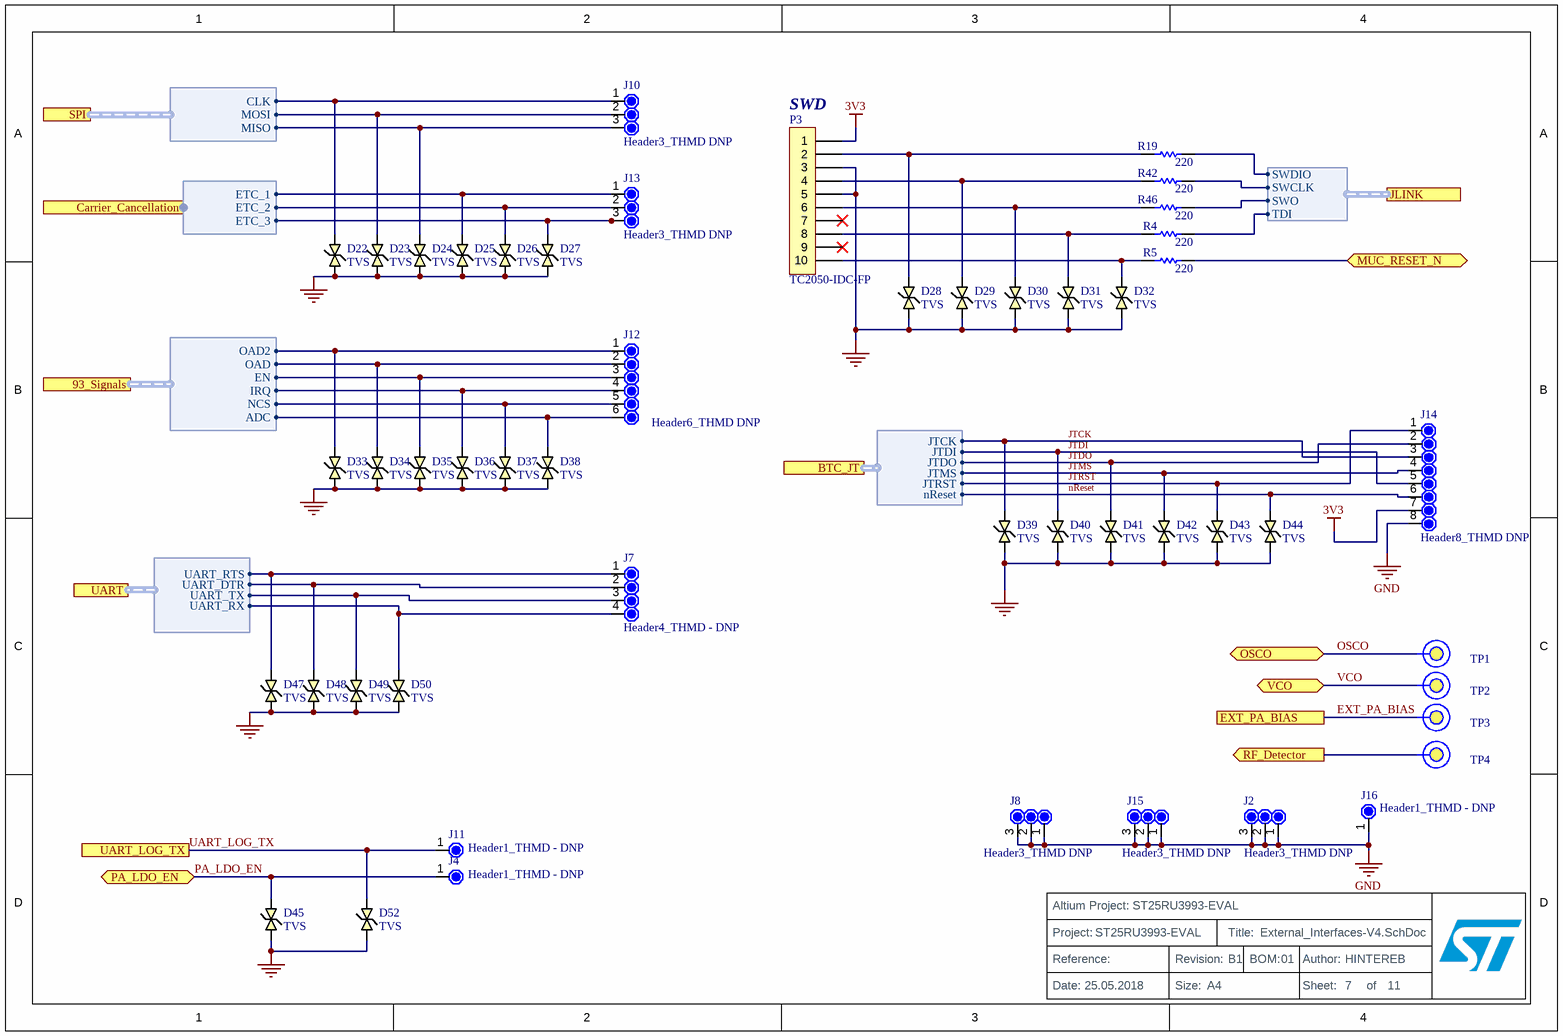
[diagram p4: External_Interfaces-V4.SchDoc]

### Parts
D22  TVS  [DFN35P60X33-2N]
D23  TVS  [DFN35P60X33-2N]
D24  TVS  [DFN35P60X33-2N]
D25  TVS  [DFN35P60X33-2N]
D26  TVS  [DFN35P60X33-2N]
D27  TVS  [DFN35P60X33-2N]
D28  TVS  [DFN35P60X33-2N]
D29  TVS  [DFN35P60X33-2N]
D30  TVS  [DFN35P60X33-2N]
D31  TVS  [DFN35P60X33-2N]
D32  TVS  [DFN35P60X33-2N]
D33  TVS  [DFN35P60X33-2N]
D34  TVS  [DFN35P60X33-2N]
D35  TVS  [DFN35P60X33-2N]
D36  TVS  [DFN35P60X33-2N]
D37  TVS  [DFN35P60X33-2N]
D38  TVS  [DFN35P60X33-2N]
D39  TVS  [DFN35P60X33-2N]
D40  TVS  [DFN35P60X33-2N]
D41  TVS  [DFN35P60X33-2N]
D42  TVS  [DFN35P60X33-2N]
D43  TVS  [DFN35P60X33-2N]
D44  TVS  [DFN35P60X33-2N]
D45  TVS  [DFN35P60X33-2N]
D47  TVS  [DFN35P60X33-2N]
D48  TVS  [DFN35P60X33-2N]
D49  TVS  [DFN35P60X33-2N]
D50  TVS  [DFN35P60X33-2N]
D52  TVS  [DFN35P60X33-2N]
J2  Header3_THMD DNP  [PLUG_THMD_STRIP3]  (no BOM)
J4  Header1_THMD - DNP  [PLUG_THMD_STRIP1]  (no BOM)
J7  Header4_THMD - DNP  [PLUG_THMD_STRIP4]  (no BOM)
J8  Header3_THMD DNP  [PLUG_THMD_STRIP3]  (no BOM)
J10  Header3_THMD DNP  [PLUG_THMD_STRIP3]  (no BOM)
J11  Header1_THMD - DNP  [PLUG_THMD_STRIP1]  (no BOM)
J12  Header6_THMD DNP  [PLUG_THMD_STRIP6]  (no BOM)
J13  Header3_THMD DNP  [PLUG_THMD_STRIP3]  (no BOM)
J14  Header8_THMD DNP  [PLUG_THMD_STRIP8]  (no BOM)
J15  Header3_THMD DNP  [PLUG_THMD_STRIP3]  (no BOM)
J16  Header1_THMD - DNP  [PLUG_THMD_STRIP1]  (no BOM)
P3  TC2050-IDC-FP  [TC2050-IDC-FP]  (no BOM)
R4  220
R5  220
R19  220
R42  220
R46  220
TitleBlock1  Title_Block  (value not drawn)  (no BOM)
TP1  Testpoint  [TP]  (value not drawn)  (no BOM)
TP2  Testpoint  [TP]  (value not drawn)  (no BOM)
TP3  Testpoint  [TP]  (value not drawn)  (no BOM)
TP4  Testpoint  [TP]  (value not drawn)  (no BOM)

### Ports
93_Signals (harness Harness_93), BTC_JT (harness Harness_BTC_JT), Carrier_Cancellation (harness Harness_CC), EXT_PA_BIAS, JLINK (harness Harness_JLINK), MUC_RESET_N (bidir), OSCO (bidir), PA_LDO_EN (bidir), RF_Detector (out), SPI (harness Harness_SPI), UART (harness Harness_UART), UART_LOG_TX, VCO (bidir)

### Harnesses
Harness_SPI: MISO, MOSI, CLK
Harness_93: IRQ, EN, NCS, ADC, OAD, OAD2
Harness_CC: ETC_1, ETC_2, ETC_3
Harness_JLINK: SWDIO, SWCLK, SWO, TDI
Harness_BTC_JT: JTMS, JTRST, nReset, JTDO, JTDI, JTCK
Harness_UART: UART_RTS, UART_DTR, UART_TX, UART_RX

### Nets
3V3: J14.7 P3.1
GND: D22.2 D23.2 D24.2 D25.2 D26.2 D27.2 D28.2 D29.2 D30.2 D31.2 D32.2 D33.2 D34.2 D35.2 D36.2 D37.2 D38.2 D39.2 D40.2 D41.2 D42.2 D43.2 D44.2 D45.2 D47.2 D48.2 D49.2 D50.2 D52.2 J2.1 J2.2 J2.3 J8.1 J8.2 J8.3 J14.8 J15.1 J15.2 J15.3 J16.1 P3.3 P3.5
ADC: D38.1 J12.6 ; port 93_Signals.ADC
CLK: D22.1 J10.1 ; port SPI.CLK
Detector: TP4.1 ; port RF_Detector
DTR: D48.1 J7.2 ; port UART.UART_DTR
EN: D35.1 J12.3 ; port 93_Signals.EN
ETC_1: D25.1 J13.1 ; port Carrier_Cancellation.ETC_1
ETC_2: D26.1 J13.2 ; port Carrier_Cancellation.ETC_2
ETC_3: D27.1 J13.3 ; port Carrier_Cancellation.ETC_3
EXT_PA_BIAS: TP3.1 ; port EXT_PA_BIAS
IRQ: D36.1 J12.4 ; port 93_Signals.IRQ
JTCK: D39.1 J14.3 ; port BTC_JT.JTCK
JTDI: D40.1 J14.5 ; port BTC_JT.JTDI
JTDO: D41.1 J14.2 ; port BTC_JT.JTDO
JTMS: D42.1 J14.4 ; port BTC_JT.JTMS
JTRST: D43.1 J14.1 ; port BTC_JT.JTRST
MISO: D24.1 J10.3 ; port SPI.MISO
MOSI: D23.1 J10.2 ; port SPI.MOSI
NCS: D37.1 J12.5 ; port 93_Signals.NCS
nReset: D44.1 J14.6 ; port BTC_JT.nReset
OAD: D34.1 J12.2 ; port 93_Signals.OAD
OAD2: D33.1 J12.1 ; port 93_Signals.OAD2
OSCO: TP1.1 ; port OSCO
PA_LDO_EN: D45.1 J4.1 ; port PA_LDO_EN
RTS: D47.1 J7.1 ; port UART.UART_RTS
RX: D50.1 J7.4 ; port UART.UART_RX
TX: D49.1 J7.3 ; port UART.UART_TX
UART_LOG_TX: D52.1 J11.1 ; port UART_LOG_TX
VCO: TP2.1 ; port VCO
NetB1_1: R5.2 ; port MUC_RESET_N
NetD28_1: D28.1 P3.2 R19.1
NetD29_1: D29.1 P3.4 R42.1
NetD30_1: D30.1 P3.6 R46.1
NetD31_1: D31.1 P3.8 R4.1
NetD32_1: D32.1 P3.10 R5.1
NetR4_2: R4.2 ; port JLINK.TDI
NetR19_2: R19.2 ; port JLINK.SWDIO
NetR42_2: R42.2 ; port JLINK.SWCLK
NetR46_2: R46.2 ; port JLINK.SWO

Not connected (* = marked no-connect by the designer): P3 7* 9*

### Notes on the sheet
- (near P3) SWD

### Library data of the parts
D22-D45 D47-D50 D52 = ESDAXLC6-1BU2: TVS DIODE 3VWM 17VC ST0201; Manufacturer: STMicroelectronics; Type: Zener; Voltage - Reverse Standoff (Typ): 3V; Voltage - Breakdown (Min): 6V; Voltage - Clamping (Max) @ Ipp: 17V; Current - Peak Pulse (10/1000µs): 1A (8/20µs); Power - Peak Pulse: 40W; Power Line Protection: No; Capacitance @ Frequency: 0.4pF @ 200MHz ~ 3GHz; Tolerance: ±1%; Power (Watts): 0.1W, 1/10W; Temperature Coefficient: ±100ppm/°C
J2 J8 J10 J13 J15 = Pin_Header_x3: Manufacturer: Wurth Electronics Inc.; Manufacturer Part Number: 61300311121; Connector Type: Header; Pitch - Mating: 0.100" (2.54mm); Number of Positions: 3; Number of Positions Loaded: All; Style: Board to Board or Cable; Shrouding: Unshrouded; Contact Length - Mating: 0.236" (6.00mm); Contact Length - Post: 0.118" (3.00mm); Overall Contact Length: 0.454" (11.54mm); Material Flammability Rating: UL94 V-0; Current Rating: 3A; Voltage Rating: 250V; Exact Component Match: no
J4 J11 J16 = Pin_Header_x1: Manufacturer: Wurth Electronics Inc.; Manufacturer Part Number: 61300211121; Connector Type: Header; Pitch - Mating: 0.100" (2.54mm); Number of Positions: 2; Number of Positions Loaded: All; Style: Board to Board or Cable; Shrouding: Unshrouded; Contact Length - Mating: 0.236" (6.00mm); Contact Length - Post: 0.118" (3.00mm); Overall Contact Length: 0.454" (11.54mm); Material Flammability Rating: UL94 V-0; Current Rating: 3A; Voltage Rating: 250V; Exact Component Match: no
J7 = Pin_Header_x4: Manufacturer: TE Connectivity AMP Connectors; Manufacturer Part Number: 3-644456-4; Connector Type: Header; Pitch - Mating: 0.100" (2.54mm); Number of Positions: 4; Number of Positions Loaded: All; Style: Board to Cable/Wire; Shrouding: Unshrouded; Contact Length - Mating: 0.295" (7.49mm); Contact Length - Post: 0.110" (2.79mm); Overall Contact Length: 0.505" (12.83mm); Material Flammability Rating: UL94 V-0; Current Rating: Varies by Wire Gauge; Voltage Rating: 250VAC; Exact Component Match: no
J12 = Pin_Header_x6: Manufacturer: Amphenol FCI; Manufacturer Part Number: 10114828-10102LF; Connector Type: Header, Shrouded; Pitch: 0.049" (1.25mm); Number of Positions: 2; Number of Positions Loaded: All; Exact Component Match: no
J14 = Pin_Header_x8: Manufacturer: TE Connectivity AMP Connectors; Manufacturer Part Number: 3-644456-8; Connector Type: Header; Pitch - Mating: 0.100" (2.54mm); Number of Positions: 8; Number of Positions Loaded: All; Style: Board to Cable/Wire; Shrouding: Unshrouded; Contact Length - Mating: 0.295" (7.49mm); Contact Length - Post: 0.110" (2.79mm); Overall Contact Length: 0.505" (12.83mm); Material Flammability Rating: UL94 V-0; Current Rating: Varies by Wire Gauge; Voltage Rating: 250VAC; Exact Component Match: no
P3 = TC2050-IDC-FP: Exact Component Match: no
R4 R5 R19 R42 R46 = RC0402JR-07220RL: RES SMD 220 OHM 5% 1/16W 0402; Manufacturer: Yageo; Power (Watts): 0.063W, 1/16W; Temperature Coefficient: ±100ppm/°C; Exact Component Match: no
TitleBlock1 = Title_Block: Exact Component Match: no
TP1-TP4 = Testpoint: Exact Component Match: no

## Sheet Controller-V4.SchDoc
size A4; SheetNumber: 5; PageSetup: Record=PageOptions¦CenterHorizontal=True¦CenterVertical=True¦PrintScale=0.97¦XCorrection=1.00¦YCorrection=1.00¦PrintKind=0¦BorderSize=5000000¦LeftOffset=0¦BottomOffset=0¦Orientation=2¦PaperLength=1000¦PaperWidth=1000¦Scale=100¦PaperSource=7¦PrintQuality=-4¦MediaType=1¦DitherType=10¦PaperKind=A4¦PrintScaleMode=1
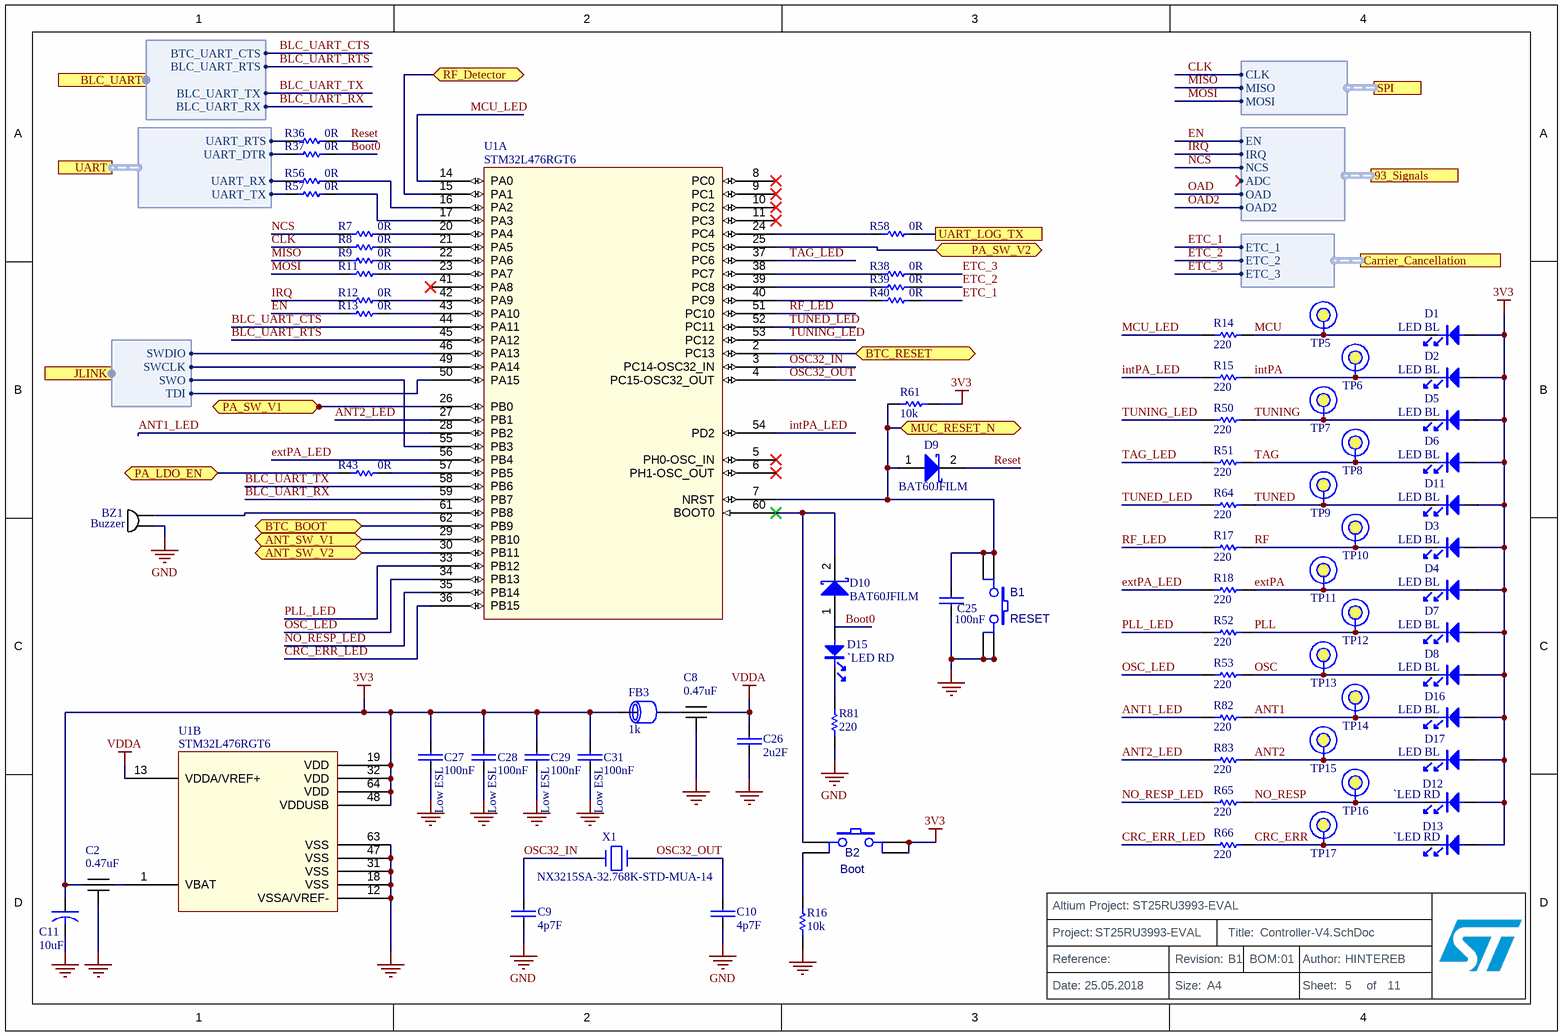
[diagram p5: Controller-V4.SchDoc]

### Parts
B1  RESET  [SW_SPST_KMR211G]
B2  Boot  [SW_SPST_KMR211G]
BZ1  Buzzer  [PKMCS0909E Series]
C2  0.47uF  [NFM18PS]
C8  0.47uF  [NFM18PS]
C9  4p7F  [C0402-RF]
C10  4p7F  [C0402-RF]
C11  10uF  [2917(7343)]
C25  100nF  [C0402-RF]
C26  2u2F  [C0201-RF]
C27  100nF  Features: Low ESL  [C0402-LLL]
C28  100nF  Features: Low ESL  [C0402-LLL]
C29  100nF  Features: Low ESL  [C0402-LLL]
C31  100nF  Features: Low ESL  [C0402-LLL]
D1  LED BL  [LNJ947W8CRA]
D2  LED BL  [LNJ947W8CRA]
D3  LED BL  [LNJ947W8CRA]
D4  LED BL  [LNJ947W8CRA]
D5  LED BL  [LNJ947W8CRA]
D6  LED BL  [LNJ947W8CRA]
D7  LED BL  [LNJ947W8CRA]
D8  LED BL  [LNJ947W8CRA]
D9  BAT60JFILM  [SOD-232]
D10  BAT60JFILM  [SOD-232]
D11  LED BL  [LNJ947W8CRA]
D12  `LED RD  [LNJ947W8CRA]
D13  `LED RD  [LNJ947W8CRA]
D15  `LED RD  [LNJ947W8CRA]
D16  LED BL  [LNJ947W8CRA]
D17  LED BL  [LNJ947W8CRA]
FB3  1k  [L0402-RF]
R7  0R  [R0402-RF]
R8  0R  [R0402-RF]
R9  0R  [R0402-RF]
R11  0R  [R0402-RF]
R12  0R  [R0402-RF]
R13  0R  [R0402-RF]
R14  220
R15  220
R16  10k  [R0402-RF]
R17  220
R18  220
R36  0R  [R0402-RF]
R37  0R  [R0402-RF]
R38  0R  [R0402-RF]
R39  0R  [R0402-RF]
R40  0R  [R0402-RF]
R43  0R  [R0402-RF]
R50  220
R51  220
R52  220
R53  220
R56  0R  [R0402-RF]
R57  0R  [R0402-RF]
R58  0R  [R0402-RF]
R61  10k  [R0402-RF]
R64  220
R65  220
R66  220
R81  220
R82  220
R83  220
TitleBlock2  Title_Block  (value not drawn)  (no BOM)
TP5  Testpoint  [TP]  (value not drawn)  (no BOM)
TP6  Testpoint  [TP]  (value not drawn)  (no BOM)
TP7  Testpoint  [TP]  (value not drawn)  (no BOM)
TP8  Testpoint  [TP]  (value not drawn)  (no BOM)
TP9  Testpoint  [TP]  (value not drawn)  (no BOM)
TP10  Testpoint  [TP]  (value not drawn)  (no BOM)
TP11  Testpoint  [TP]  (value not drawn)  (no BOM)
TP12  Testpoint  [TP]  (value not drawn)  (no BOM)
TP13  Testpoint  [TP]  (value not drawn)  (no BOM)
TP14  Testpoint  [TP]  (value not drawn)  (no BOM)
TP15  Testpoint  [TP]  (value not drawn)  (no BOM)
TP16  Testpoint  [TP]  (value not drawn)  (no BOM)
TP17  Testpoint  [TP]  (value not drawn)  (no BOM)
U1  STM32L476RGT6  [LQFP64-10x10mm]  (parts A,B of 2)
X1  NX3215SA-32.768K-STD-MUA-14  [NX3215SA-32.768K-STD-MUA-8]

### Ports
93_Signals (harness Harness_93), ANT_SW_V1 (bidir), ANT_SW_V2 (bidir), BLC_UART (harness Harness_UART_BT), BTC_BOOT (bidir), BTC_RESET (bidir), Carrier_Cancellation (harness Harness_CC), JLINK (harness Harness_JLINK), MUC_RESET_N (bidir), PA_LDO_EN (bidir), PA_SW_V1 (bidir), PA_SW_V2 (bidir), RF_Detector (bidir), SPI (harness Harness_SPI), UART (harness Harness_UART), UART_LOG_TX

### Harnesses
Harness_SPI: MISO, MOSI, CLK
Harness_93: IRQ, EN, NCS, ADC, OAD, OAD2
Harness_CC: ETC_1, ETC_2, ETC_3
Harness_JLINK: SWDIO, SWCLK, SWO, TDI
Harness_UART: UART_RTS, UART_DTR, UART_TX, UART_RX
Harness_UART_BT: BLC_UART_RTS, BTC_UART_CTS, BLC_UART_TX, BLC_UART_RX

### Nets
3V3: B2.1 B2.4 C2.1 C11.1 C27.1 C28.1 C29.1 C31.1 D1.1 D2.1 D3.1 D4.1 D5.1 D6.1 D7.1 D8.1 D11.1 D12.1 D13.1 D16.1 D17.1 FB3.1 R61.1 U1.19(VDD) U1.32(VDD) U1.48(VDDUSB) U1.64(VDD)
GND: B1.2 B1.3 BZ1.2 C2.2 C8.2 C9.2 C10.2 C11.2 C25.2 C26.2 C27.2 C28.2 C29.2 C31.2 R16.1 R81.1 U1.12(VSSA/VREF-) U1.18(VSS) U1.31(VSS) U1.47(VSS) U1.63(VSS)
VDDA: C8.3 C26.1 U1.13(VDDA/VREF+)
ANT1: D16.2 R82.2 TP14.1
ANT1_LED: R82.1 U1.28(PB2)
ANT2: D17.2 R83.2 TP15.1
ANT2_LED: R83.1 U1.27(PB1)
BLC_UART_CTS: U1.44(PA11) ; port BLC_UART.BTC_UART_CTS
BLC_UART_RTS: U1.45(PA12) ; port BLC_UART.BLC_UART_RTS
BLC_UART_RX: U1.59(PB7) ; port BLC_UART.BLC_UART_RX
BLC_UART_TX: U1.58(PB6) ; port BLC_UART.BLC_UART_TX
Boot0: D10.1(A) D15.1 R37.2
CLK: R8.1 ; port SPI.CLK
CRC_ERR: D13.2 R66.2 TP17.1
CRC_ERR_LED: R66.1 U1.36(PB15)
Detector: U1.15(PA1) ; port RF_Detector
DTR: R37.1 ; port UART.UART_DTR
EN: R13.1 ; port 93_Signals.EN
ETC_1: R40.2 ; port Carrier_Cancellation.ETC_1
ETC_2: R39.2 ; port Carrier_Cancellation.ETC_2
ETC_3: R38.2 ; port Carrier_Cancellation.ETC_3
extPA: D4.2 R18.2 TP11.1
extPA_LED: R18.1 U1.56(PB4)
intPA: D2.2 R15.2 TP6.1
intPA_LED: R15.1 U1.54(PD2)
IRQ: R12.1 ; port 93_Signals.IRQ
MCU: D1.2 R14.2 TP5.1
MCU_LED: R14.1 U1.14(PA0)
MISO: R9.1 ; port SPI.MISO
MOSI: R11.1 ; port SPI.MOSI
NCS: R7.1 ; port 93_Signals.NCS
NO_RESP: D12.2 R65.2 TP16.1
NO_RESP_LED: R65.1 U1.35(PB14)
OSC: D8.2 R53.2 TP13.1
OSC32_IN: C9.1 U1.3(PC14-OSC32_IN) X1.1
OSC32_OUT: C10.1 U1.4(PC15-OSC32_OUT) X1.2
OSC_LED: R53.1 U1.34(PB13)
PA_LDO_EN: R43.1 ; port PA_LDO_EN
PLL: D7.2 R52.2 TP12.1
PLL_LED: R52.1 U1.33(PB12)
Reset: D9.2(K) R36.2
RF: D3.2 R17.2 TP10.1
RF_LED: R17.1 U1.51(PC10)
RTS: R36.1 ; port UART.UART_RTS
RX: R56.1 ; port UART.UART_RX
TAG: D6.2 R51.2 TP8.1
TAG_LED: R51.1 U1.37(PC6)
TUNED: D11.2 R64.2 TP9.1
TUNED_LED: R64.1 U1.52(PC11)
TUNING: D5.2 R50.2 TP7.1
TUNING_LED: R50.1 U1.53(PC12)
TX: R57.1 ; port UART.UART_TX
UART_LOG_TX: R58.2 ; port UART_LOG_TX
NetB1_1: B1.1 B1.4 C25.1 D9.1(A) R61.2 U1.7(NRST) ; port MUC_RESET_N
NetB2_2: B2.2 D10.2(K) U1.60(BOOT0)
NetB2_3: B2.3 R16.2
NetBZ1_1: BZ1.1 U1.61(PB8)
NetC2_3: C2.3 U1.1(VBAT)
NetC8_1: C8.1 FB3.2
NetD15_2: D15.2 R81.2
NetJ19_1: U1.62(PB9) ; port BTC_BOOT
NetR4_2: U1.50(PA15) ; port JLINK.TDI
NetR7_2: R7.2 U1.20(PA4)
NetR8_2: R8.2 U1.21(PA5)
NetR9_2: R9.2 U1.22(PA6)
NetR11_2: R11.2 U1.23(PA7)
NetR12_2: R12.2 U1.42(PA9)
NetR13_2: R13.2 U1.43(PA10)
NetR19_2: U1.46(PA13) ; port JLINK.SWDIO
NetR38_1: R38.1 U1.38(PC7)
NetR39_1: R39.1 U1.39(PC8)
NetR40_1: R40.1 U1.40(PC9)
NetR42_2: U1.49(PA14) ; port JLINK.SWCLK
NetR43_2: R43.2 U1.57(PB5)
NetR46_2: U1.55(PB3) ; port JLINK.SWO
NetR56_2: R56.2 U1.16(PA2)
NetR57_2: R57.2 U1.17(PA3)
NetR58_1: R58.1 U1.24(PC4)
NetR74_1: U1.2(PC13) ; port BTC_RESET
NetS1_1: U1.26(PB0) ; port PA_SW_V1
NetS1_3: U1.25(PC5) ; port PA_SW_V2
NetS2_1: U1.29(PB10) ; port ANT_SW_V1
NetS2_3: U1.30(PB11) ; port ANT_SW_V2

Not connected (* = marked no-connect by the designer): U1 5(PH0-OSC_IN)* 6(PH1-OSC_OUT)* 8(PC0)* 9(PC1)* 10(PC2)* 11(PC3)* 41(PA8)*

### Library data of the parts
B1 B2 = SW-PUSH-CMS_BLACK_1: Non-Open Push-Button 0.1A 24V; Manufacturer 1: C&K Components; Manufacturer Part Number 1: KMR211NG LFS; Circuit: SPST-NO; Switch Function: Off-Mom; Contact Rating @ Voltage: 0.05A @ 32VDC; Actuator Type: Standard; Actuator Height off PCB, from Pins: 1.90mm; Actuator Orientation: Top Actuated; Outline: 4.60mm x 2.80mm; Illumination: Non-Illuminated; Operating Force: 120gf; Switch Travel: 0.20mm; Mechanical Life: 200,000 Cycles; Exact Component Match: no
BZ1 = PKMCS0909E4000-R1: AUDIO PIEZO TRANSDUCER 12.5V SMD; Manufacturer: Murata Electronics North America; Driver Circuitry: Transducer, Externally Driven; Input Type: Zero-Peak Signal; Voltage - Rated: 1.5V; Voltage Range: 12.5V (Max); Frequency: 4kHz; Operating Mode: Single Tone; Sound Pressure Level (SPL): 65dB @ 1.5V, 10cm; Port Location: Side; Exact Component Match: no
C2 C8 = NFM18PS474R0J3D: as C91 on sheet UHF_RFID-V4
C9 C10 = GRM1555C2A4R7CA01D: CAP CER 4.7PF 100V NP0 0402; Manufacturer 1: Murata Electronics North America; Tolerance: ±0.25pF; Temperature Coefficient: C0G, NP0; Type: kHz Crystal (Tuning Fork); Frequency: 32.768kHz; Frequency Tolerance: ±20ppm; Load Capacitance: 12.5pF; ESR (Equivalent Series Resistance): 70 kOhm; Operating Mode: Fundamental; Exact Component Match: no
C11 = ECASD41C106M060K00: as C92 on sheet UHF_RFID-V4
C25 = GRM155R71C104KA88D: as C50 on sheet UHF_RFID-V4
C26 = GRM033R60J225ME15D: as C13 on sheet UHF_RFID-V4
C27-C29 C31 = LLL153C80J104ME01E: as C67 on sheet UHF_RFID-V4
D1-D8 D11 D16 D17 = LNJ947W8CRA: LED BLUE 0402 SMD; Manufacturer 1: Panasonic Electronic Components; Millicandela Rating: 18mcd; Lens Style/Size: Rectangle with Flat Top, 0.70mm x 0.50mm; Voltage - Forward (Vf) (Typ): 2.9V; Current - Test: 5mA; Wavelength - Dominant: 472nm; Wavelength - Peak: 465nm; Exact Component Match: no
D9 D10 = BAT60JFILM: DIODE SCHOTTKY 10V 3A SOD323; Manufacturer: STMicroelectronics; Current - Average Rectified (Io): 3A (DC); Voltage - Forward (Vf) (Max) @ If: 580mV @ 1A; Speed: Fast Recovery =< 500ns, > 200mA (Io); Current - Reverse Leakage @ Vr: 6µA @ 10V; Exact Component Match: no
D12 D13 D15 = LNJ247W82RA: LED RED 0402 SMD; Manufacturer: Panasonic Electronic Components; Millicandela Rating: 16mcd; Lens Style/Size: Rectangle with Flat Top, 0.70mm x 0.50mm; Voltage - Forward (Vf) (Typ): 1.95V; Current - Test: 5mA; Wavelength - Dominant: 630nm; Wavelength - Peak: 645nm; Exact Component Match: no
FB3 = BLM15HG102SN1D: as FB4 on sheet UHF_RFID-V4
R7-R9 R11-R13 R36-R40 R43 R56-R58 = RC0402JR-070RL: as R54 on sheet UHF_RFID-V4
R14 R15 R17 R18 R50-R53 R64-R66 R81-R83 = RC0402JR-07220RL: as R4 on sheet External_Interfaces-V4
R16 R61 = RC0402FR-0710KL: RES SMD 10K OHM 1% 1/16W 0402; Manufacturer 1: Yageo; Power (Watts): 0.063W, 1/16W; Temperature Coefficient: ±100ppm/°C; Exact Component Match: no
TitleBlock2 = Title_Block: Exact Component Match: no
TP5-TP17 = Testpoint: Exact Component Match: no
U1 = STM32L476RGT6: IC MCU 32BIT 1MB FLASH 64LQFP; Manufacturer: STMicroelectronics; Core Processor: ARM® Cortex®-M4; Core Size: 32-Bit; Speed: 80MHz; Connectivity: CAN, I²C, IrDA, LIN, MMC/SD, QSPI, SAI, SPI, SWPMI, UART/USART, USB OTG; Peripherals: Brown-out Detect/Reset, DMA, LCD, PWM, WDT; Number of I/O: 51; Program Memory Size: 1MB (1M x 8); RAM Size: 128K x 8; Voltage - Supply (Vcc/Vdd): 1.71 V ~ 3.6 V; Data Converters: A/D 16x12b, D/A 2x12b; Oscillator Type: Internal; Exact Component Match: no
X1 = NX3215SA-32.768K-STD-MUA-14: CRYSTAL 32.7680KHZ 6PF SMD; Manufacturer: NDK America, Inc.; Frequency: 32.768kHz; Frequency Tolerance: ±20ppm; ESR (Equivalent Series Resistance): 70 kOhm; Operating Mode: Fundamental; Exact Component Match: no

## Sheet Carrier_Cancellation-V4.SchDoc
size A4; SheetNumber: 4; PageSetup: Record=PageOptions¦CenterHorizontal=True¦CenterVertical=True¦PrintScale=0.97¦XCorrection=1.00¦YCorrection=1.00¦PrintKind=0¦BorderSize=5000000¦LeftOffset=0¦BottomOffset=0¦Orientation=2¦PaperLength=1000¦PaperWidth=1000¦Scale=100¦PaperSource=7¦PrintQuality=-4¦MediaType=1¦DitherType=10¦PaperKind=A4¦PrintScaleMode=1
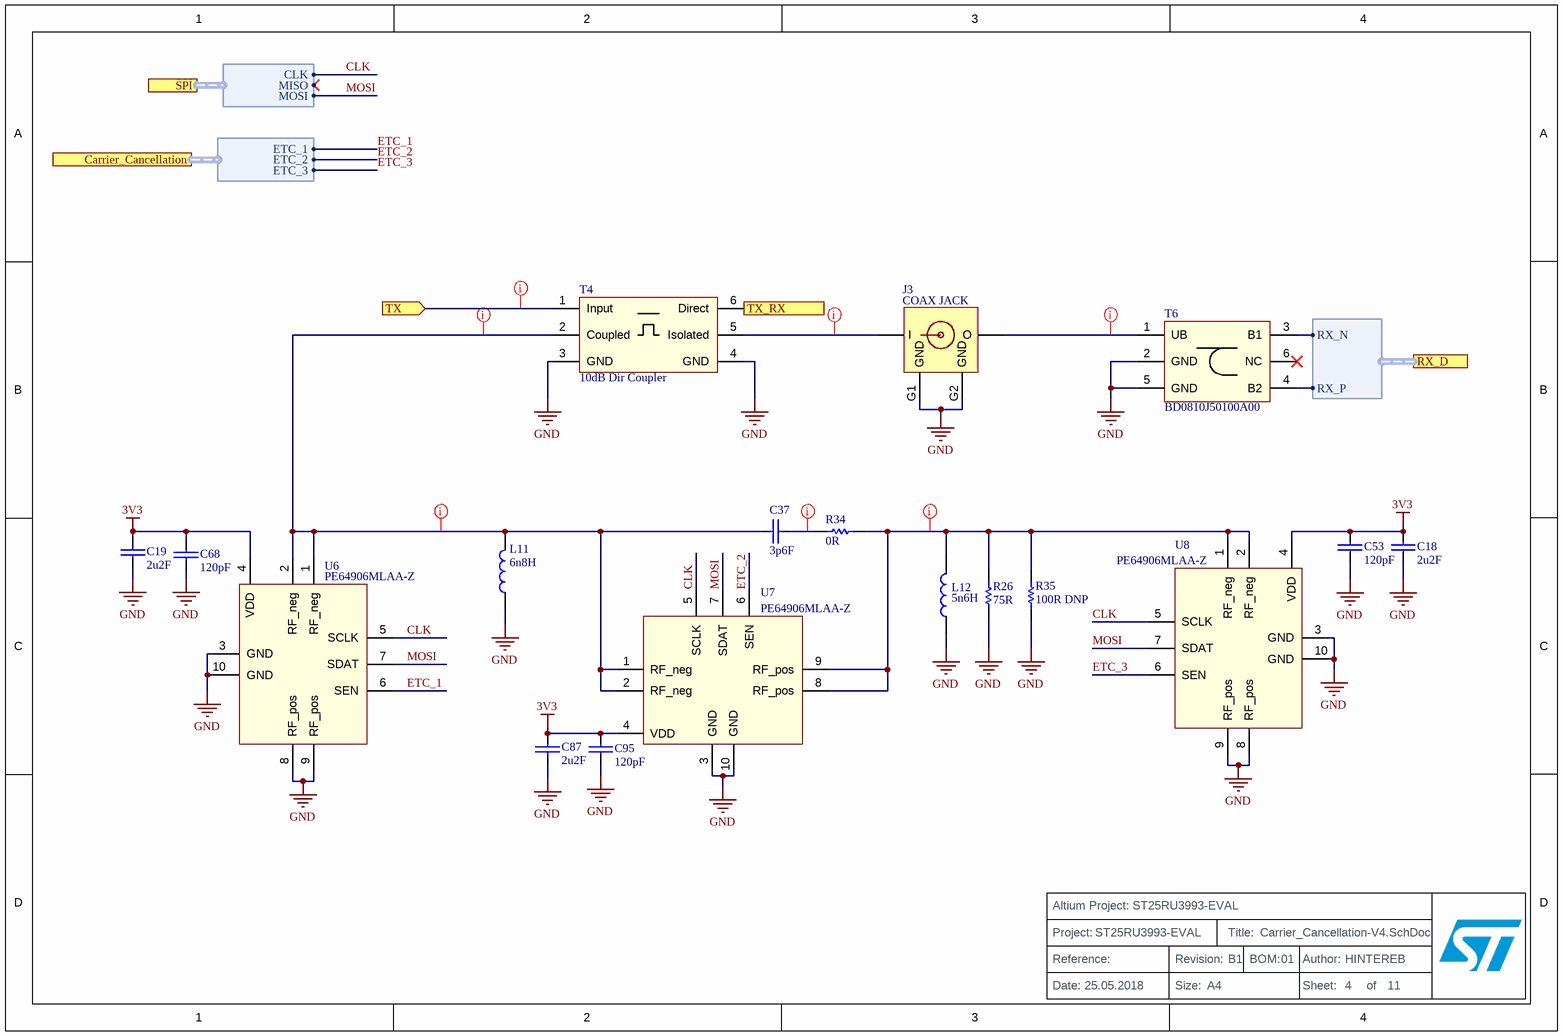
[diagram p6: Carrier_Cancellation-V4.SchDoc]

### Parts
C18  2u2F  [C0201-RF]
C19  2u2F  [C0201-RF]
C37  3p6F  [C0402-RF]
C53  120pF  [C0201-RF]
C68  120pF  [C0201-RF]
C87  2u2F  [C0201-RF]
C95  120pF  [C0201-RF]
J3  COAX JACK  [MS-156HF]
L11  6n8H  [L0402-RF]
L12  5n6H  [L0402-RF]
R26  75R  [R0402-RF]
R34  0R  [R0402-RF]
R35  100R DNP  [R0402-RF]  (no BOM)
T4  10dB Dir Coupler  [DC0710J5010AHF]
T6  BD0810J50100A00  [BD0810J50100AHF]
TitleBlock6  Title_Block  (value not drawn)  (no BOM)
U6  PE64906MLAA-Z  [PE62304]
U7  PE64906MLAA-Z  [PE62304]
U8  PE64906MLAA-Z  [PE62304]

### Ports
Carrier_Cancellation (harness Harness_CC), RX_D (harness Harness_RX_D), SPI (harness Harness_SPI), TX (in), TX_RX

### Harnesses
Harness_RX_D: RX_P, RX_N
Harness_CC: ETC_1, ETC_2, ETC_3
Harness_SPI: MISO, MOSI, CLK

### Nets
3V3: C18.1 C19.1 C53.1 C68.1 C87.1 C95.1 U6.4(VDD) U7.4(VDD) U8.4(VDD)
GND: C18.2 C19.2 C53.2 C68.2 C87.2 C95.2 J3.G1(GND) J3.G2(GND) L11.1 L12.1 R26.1 R35.1 T4.3(GND) T4.4(GND) T6.2(GND) T6.5(GND) U6.3(GND) U6.8(RF_pos) U6.9(RF_pos) U6.10(GND) U7.3(GND) U7.10(GND) U8.3(GND) U8.8(RF_pos) U8.9(RF_pos) U8.10(GND)
CLK: U6.5(SCLK) U7.5(SCLK) U8.5(SCLK) ; port SPI.CLK
ETC_1: U6.6(SEN) ; port Carrier_Cancellation.ETC_1
ETC_2: U7.6(SEN) ; port Carrier_Cancellation.ETC_2
ETC_3: U8.6(SEN) ; port Carrier_Cancellation.ETC_3
MOSI: U6.7(SDAT) U7.7(SDAT) U8.7(SDAT) ; port SPI.MOSI
RX_N: T6.3(B1) ; port RX_D.RX_N
RX_P: T6.4(B2) ; port RX_D.RX_P
NetC37_1: C37.1 L11.2 T4.2(Coupled) U6.1(RF_neg) U6.2(RF_neg) U7.1(RF_neg) U7.2(RF_neg)
NetC37_2: C37.2 R34.1
NetC112_2: T4.6(Direct) ; port TX_RX
NetJ3_IN: J3.IN(I) T4.5(Isolated)
NetJ3_OUT: J3.OUT(O) T6.1(UB)
NetL12_2: L12.2 R26.2 R34.2 R35.2 U7.8(RF_pos) U7.9(RF_pos) U8.1(RF_neg) U8.2(RF_neg)
NetT2_1: T4.1(Input) ; port TX

Not connected (* = marked no-connect by the designer): T6 6(NC)*

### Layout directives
net class SE_CPWG: NetC37_1, NetC37_2, NetJ3_IN, NetJ3_OUT, NetL12_2, NetT2_1

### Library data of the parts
C18 C19 C87 = GRM033R60J225ME15D: as C13 on sheet UHF_RFID-V4
C37 = GRM1555C1H3R6BA01D: CAP CER 3.6PF 50V C0G/NP0 0402; Manufacturer: Murata Electronics North America; Tolerance: ±0.1pF; Temperature Coefficient: C0G, NP0; Exact Component Match: yes
C53 C68 C95 = GRM0335C1H121JA01D: as C12 on sheet UHF_RFID-V4
J3 = MS-156HF: as J9 on sheet UHF_RFID-V4
L11 = LQW15AN6N8G00D: FIXED IND 6.8NH 700MA 90 MOHM; Manufacturer: Murata Electronics North America; Type: Wirewound; Material - Core: Non-Magnetic; Tolerance: ±2%; Shielding: Unshielded; DC Resistance (DCR): 90 mOhm Max; Q @ Freq: 25 @ 250MHz; Exact Component Match: yes
L12 = LQW15AN5N6C10D: Inductor RF Chip Wirewound 5.6nH 0.2nH 100MHz 30Q-Factor 800mA 51mOhm DCR 0402 T/R; Manufacturer: Murata; Core Material: Air; Self Resonant Frequency: 8GHz; Shielding: Unshielded; DC Resistance (DCR): 51mR; Q Factor: 30
R26 = ERJ-2RKF75R0X: Res Thick Film 0402 75 Ohm 1% 0.1W(1/10W) ±100ppm/C Molded SMD Automotive Punched T/R; Manufacturer: Panasonic; Voltage Rating: 50V; Power Rating: 100mW; Temperature Coefficient: 100ppm/°C
R34 = RC0402JR-070RL: as R54 on sheet UHF_RFID-V4
R35 = RC0402FR-07100RL: as R21 on sheet Power_Amplifier-V4
T4 = DC0710J5010AHF: Directional Coupler; Manufacturer: Anaren; Coupler Type: Standard; Frequency: 700MHz ~ 1GHz; Coupling Factor: 10.9dB; Insertion Loss: 0.21dB; Power - Max: 2W; Return Loss: 17.5dB; Exact Component Match: no
T6 = BD0810J50100AHF: as T5 on sheet UHF_RFID-V4
TitleBlock6 = Title_Block: Exact Component Match: no
U6-U8 = PE64906MLAA-Z: IC RF DTC 100-3000MHZ 10QFN; Manufacturer: Peregrine Semiconductor; Function: Digitally Tunable Capacitor; Frequency: 100MHz ~ 3GHz; RF Type: General Purpose; Secondary Attributes: SPI Interface; Exact Component Match: yes; Frequency - Lower: 500MHz; Isolation @ Frequency: 20dB @ 5.8GHz (typ); Insertion Loss @ Frequency: 0.8dB @ 5.8GHz; IIP3: 57dBm (typ); Circuit: SPDT; P1dB: 36dBm; Impedance: 50 Ohm; Voltage - Supply: 2.5 V ~ 5 V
